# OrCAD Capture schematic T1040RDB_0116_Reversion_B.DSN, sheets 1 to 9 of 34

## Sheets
1 01 Page Listing: title: T1040RDB; rev: A
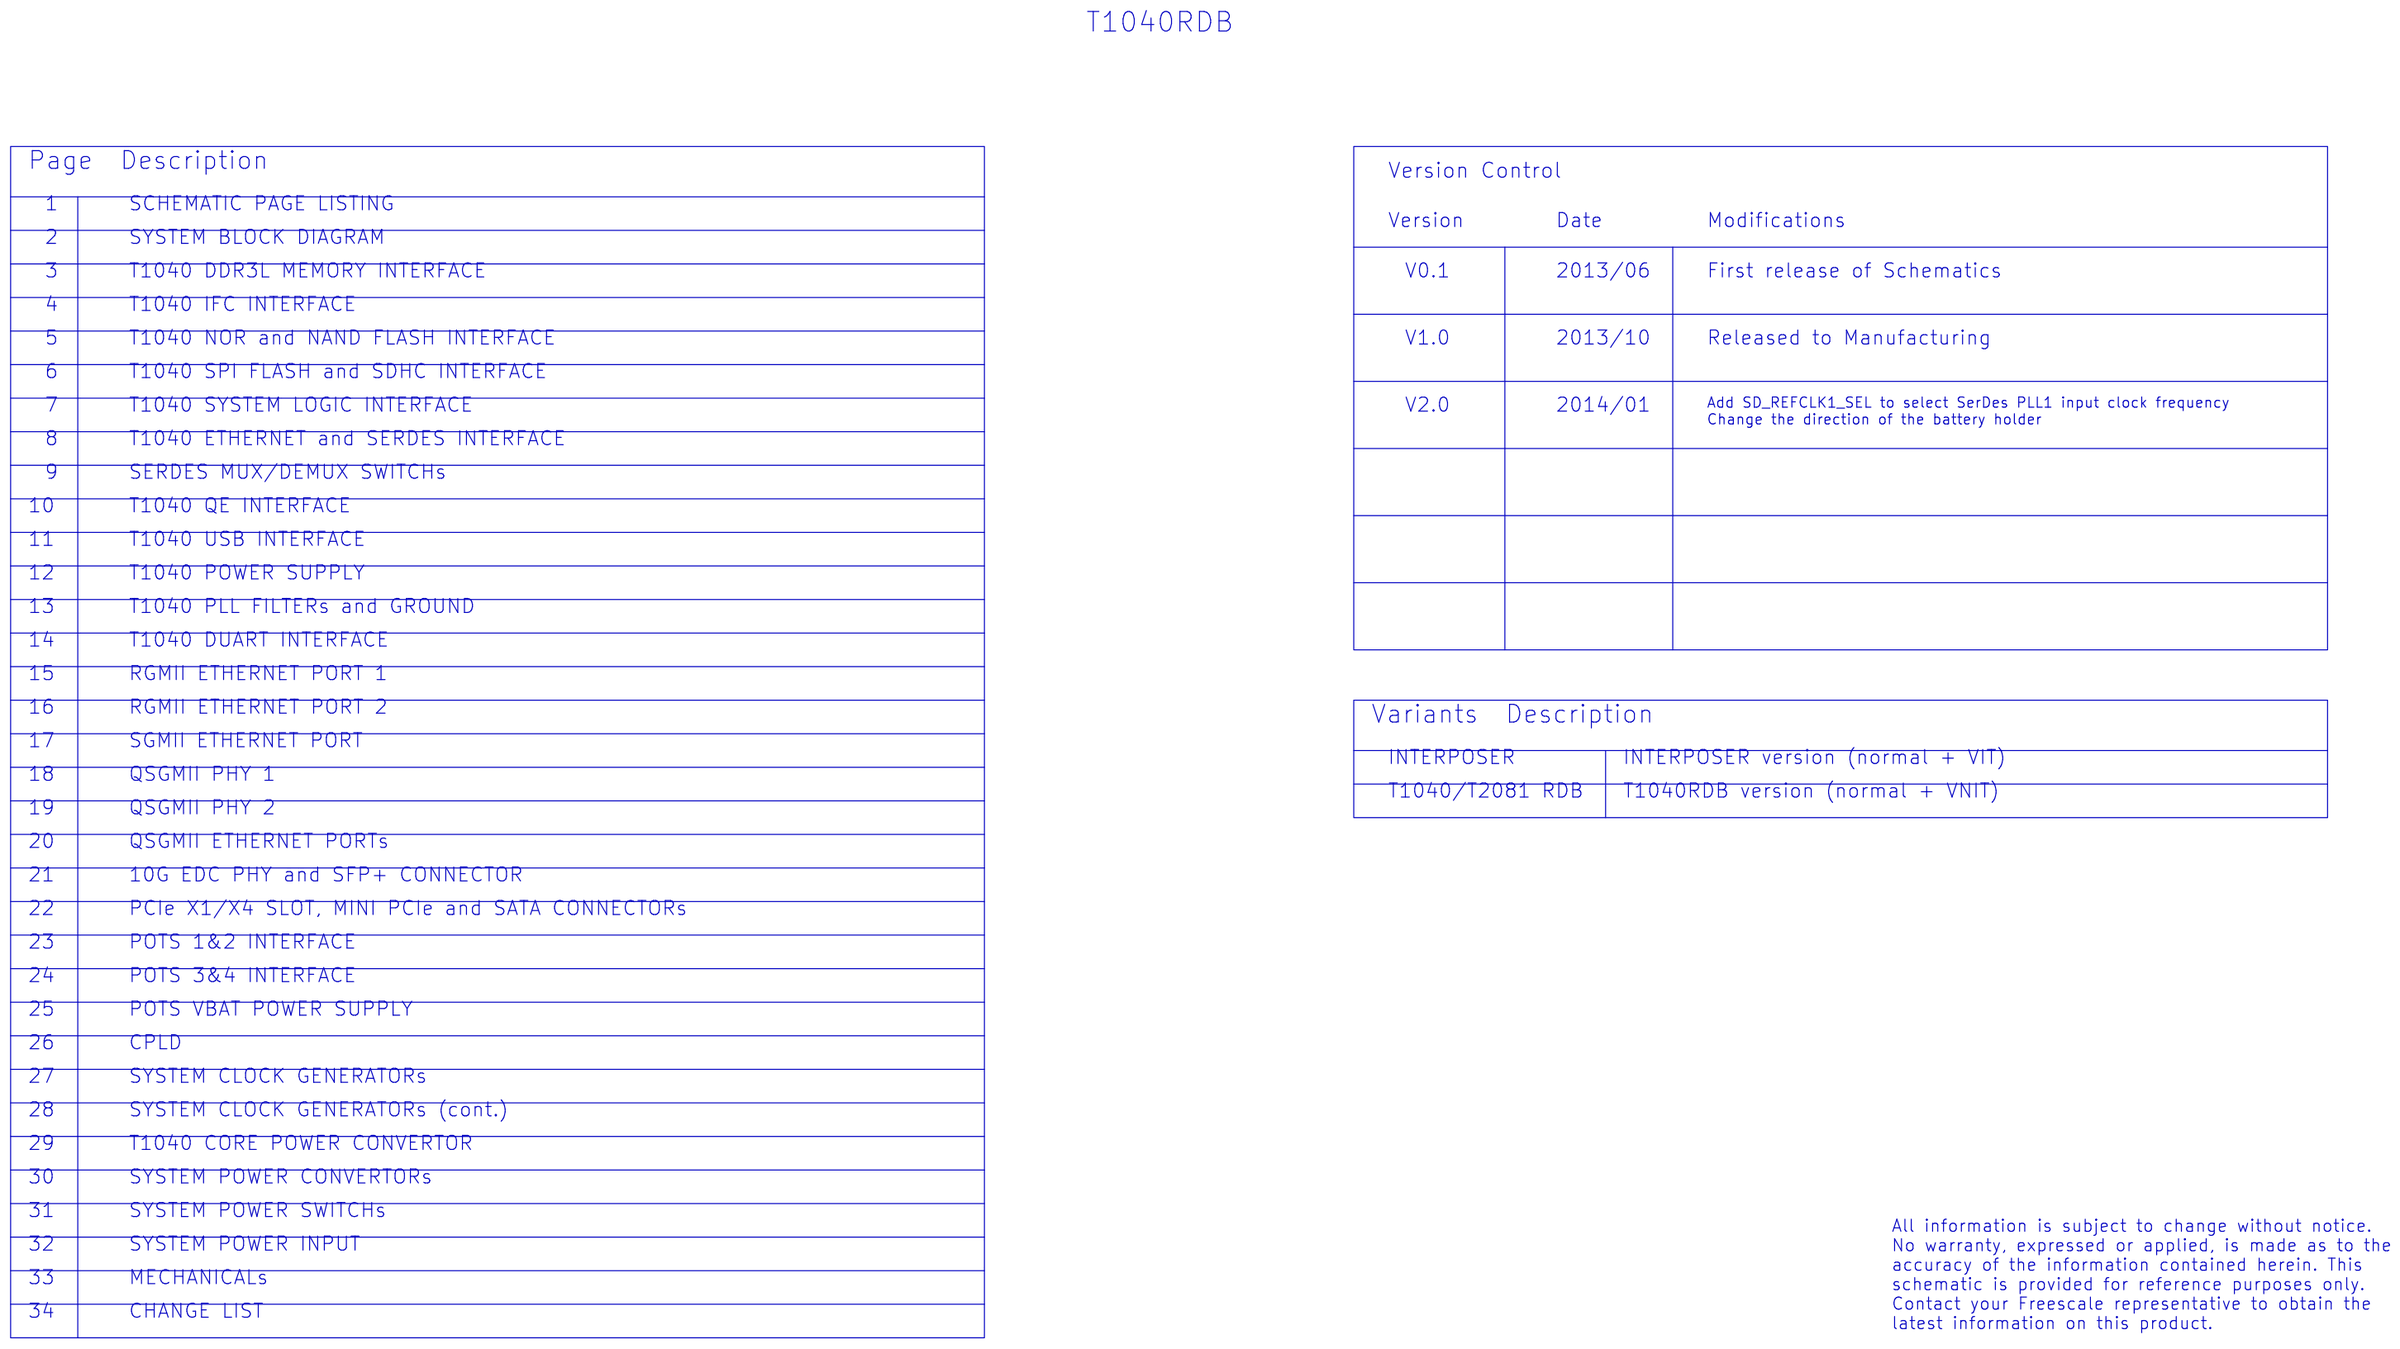
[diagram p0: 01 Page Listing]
2 02 Block Diagram
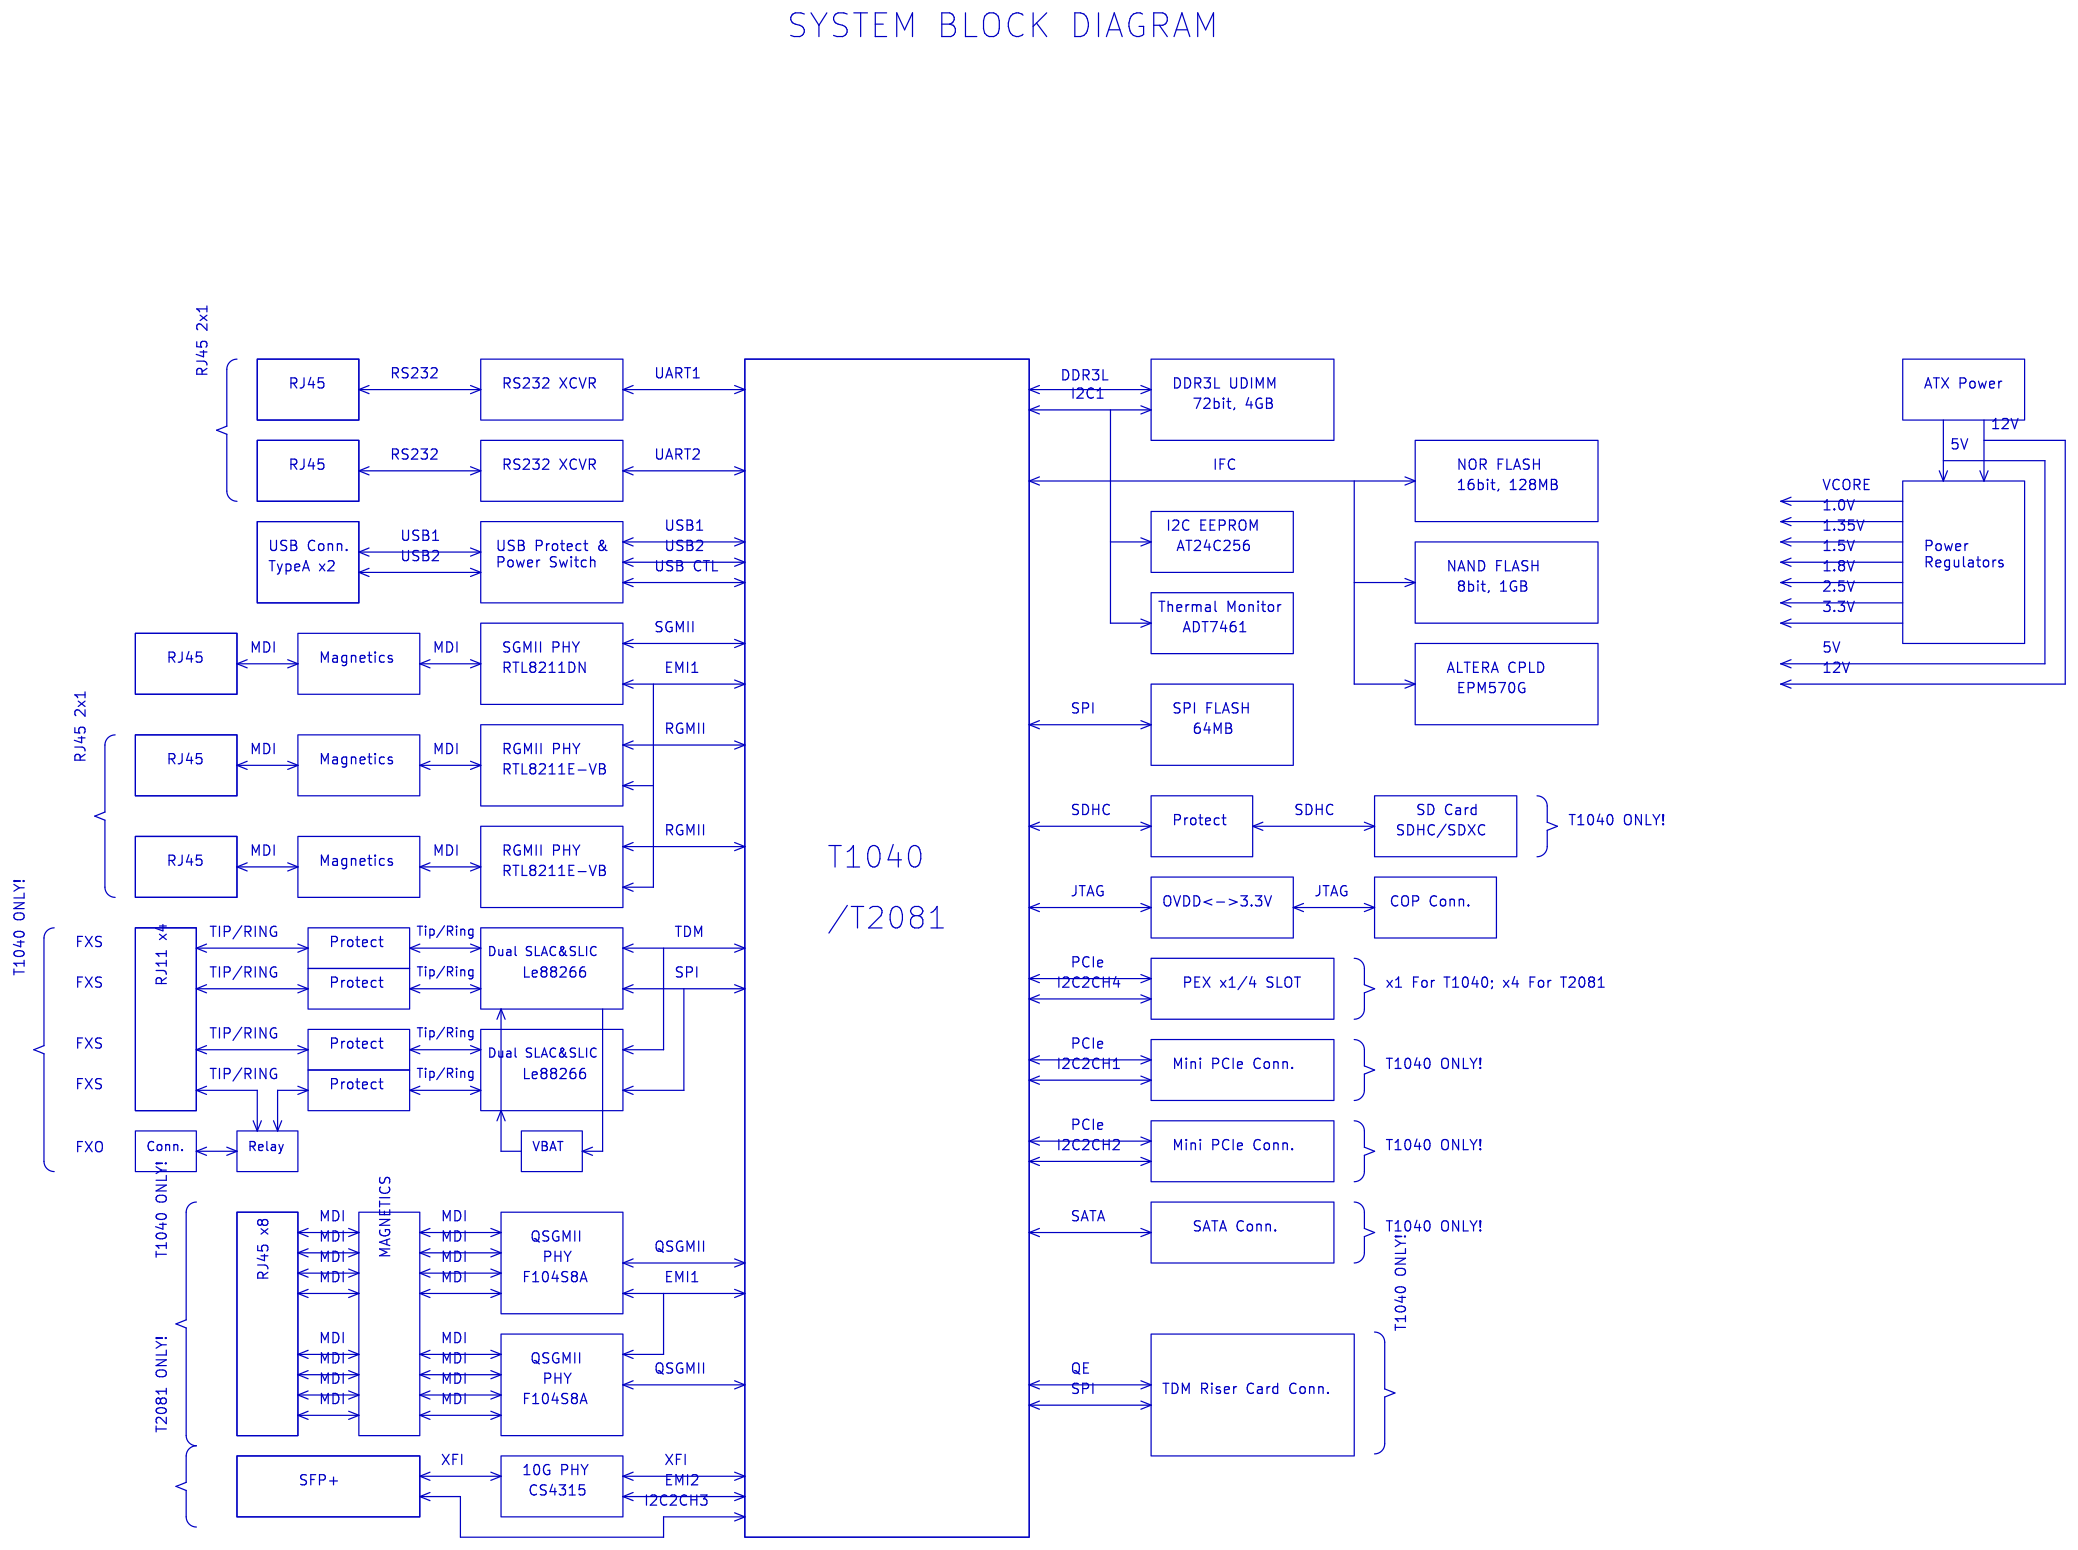
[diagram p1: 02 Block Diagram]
3 03 DDR3: size B
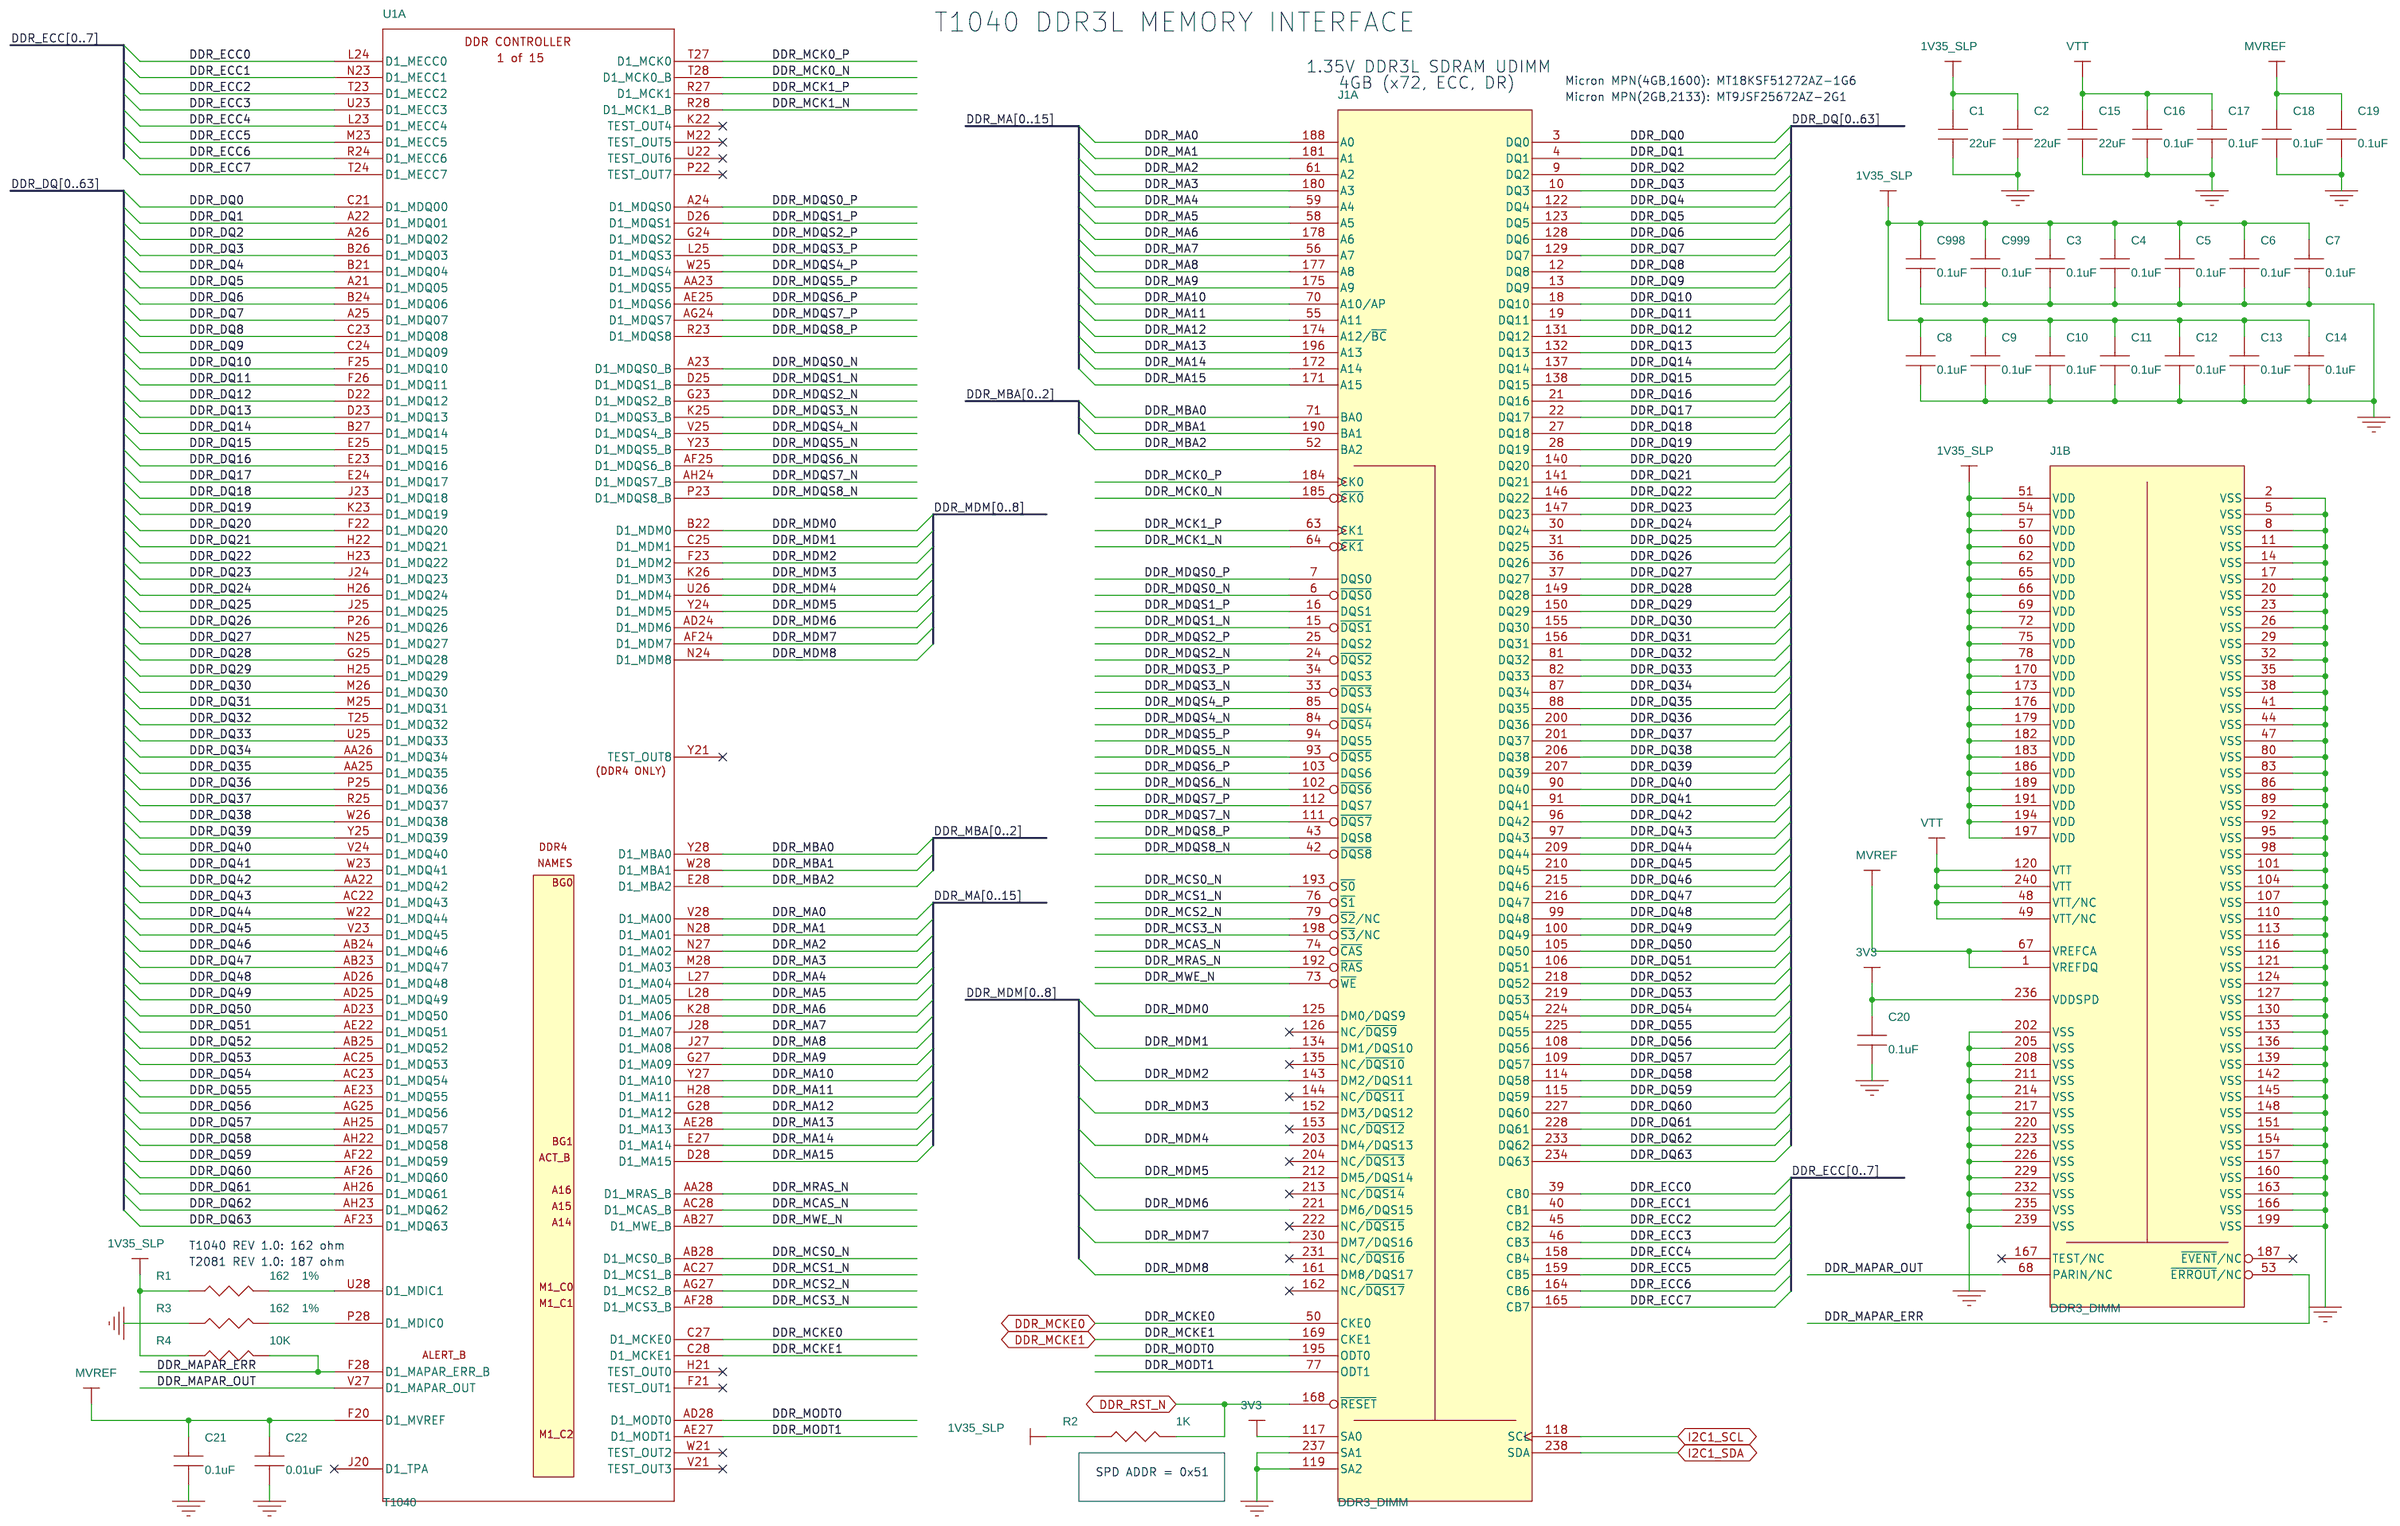
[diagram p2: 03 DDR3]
4 04 IFC: size B
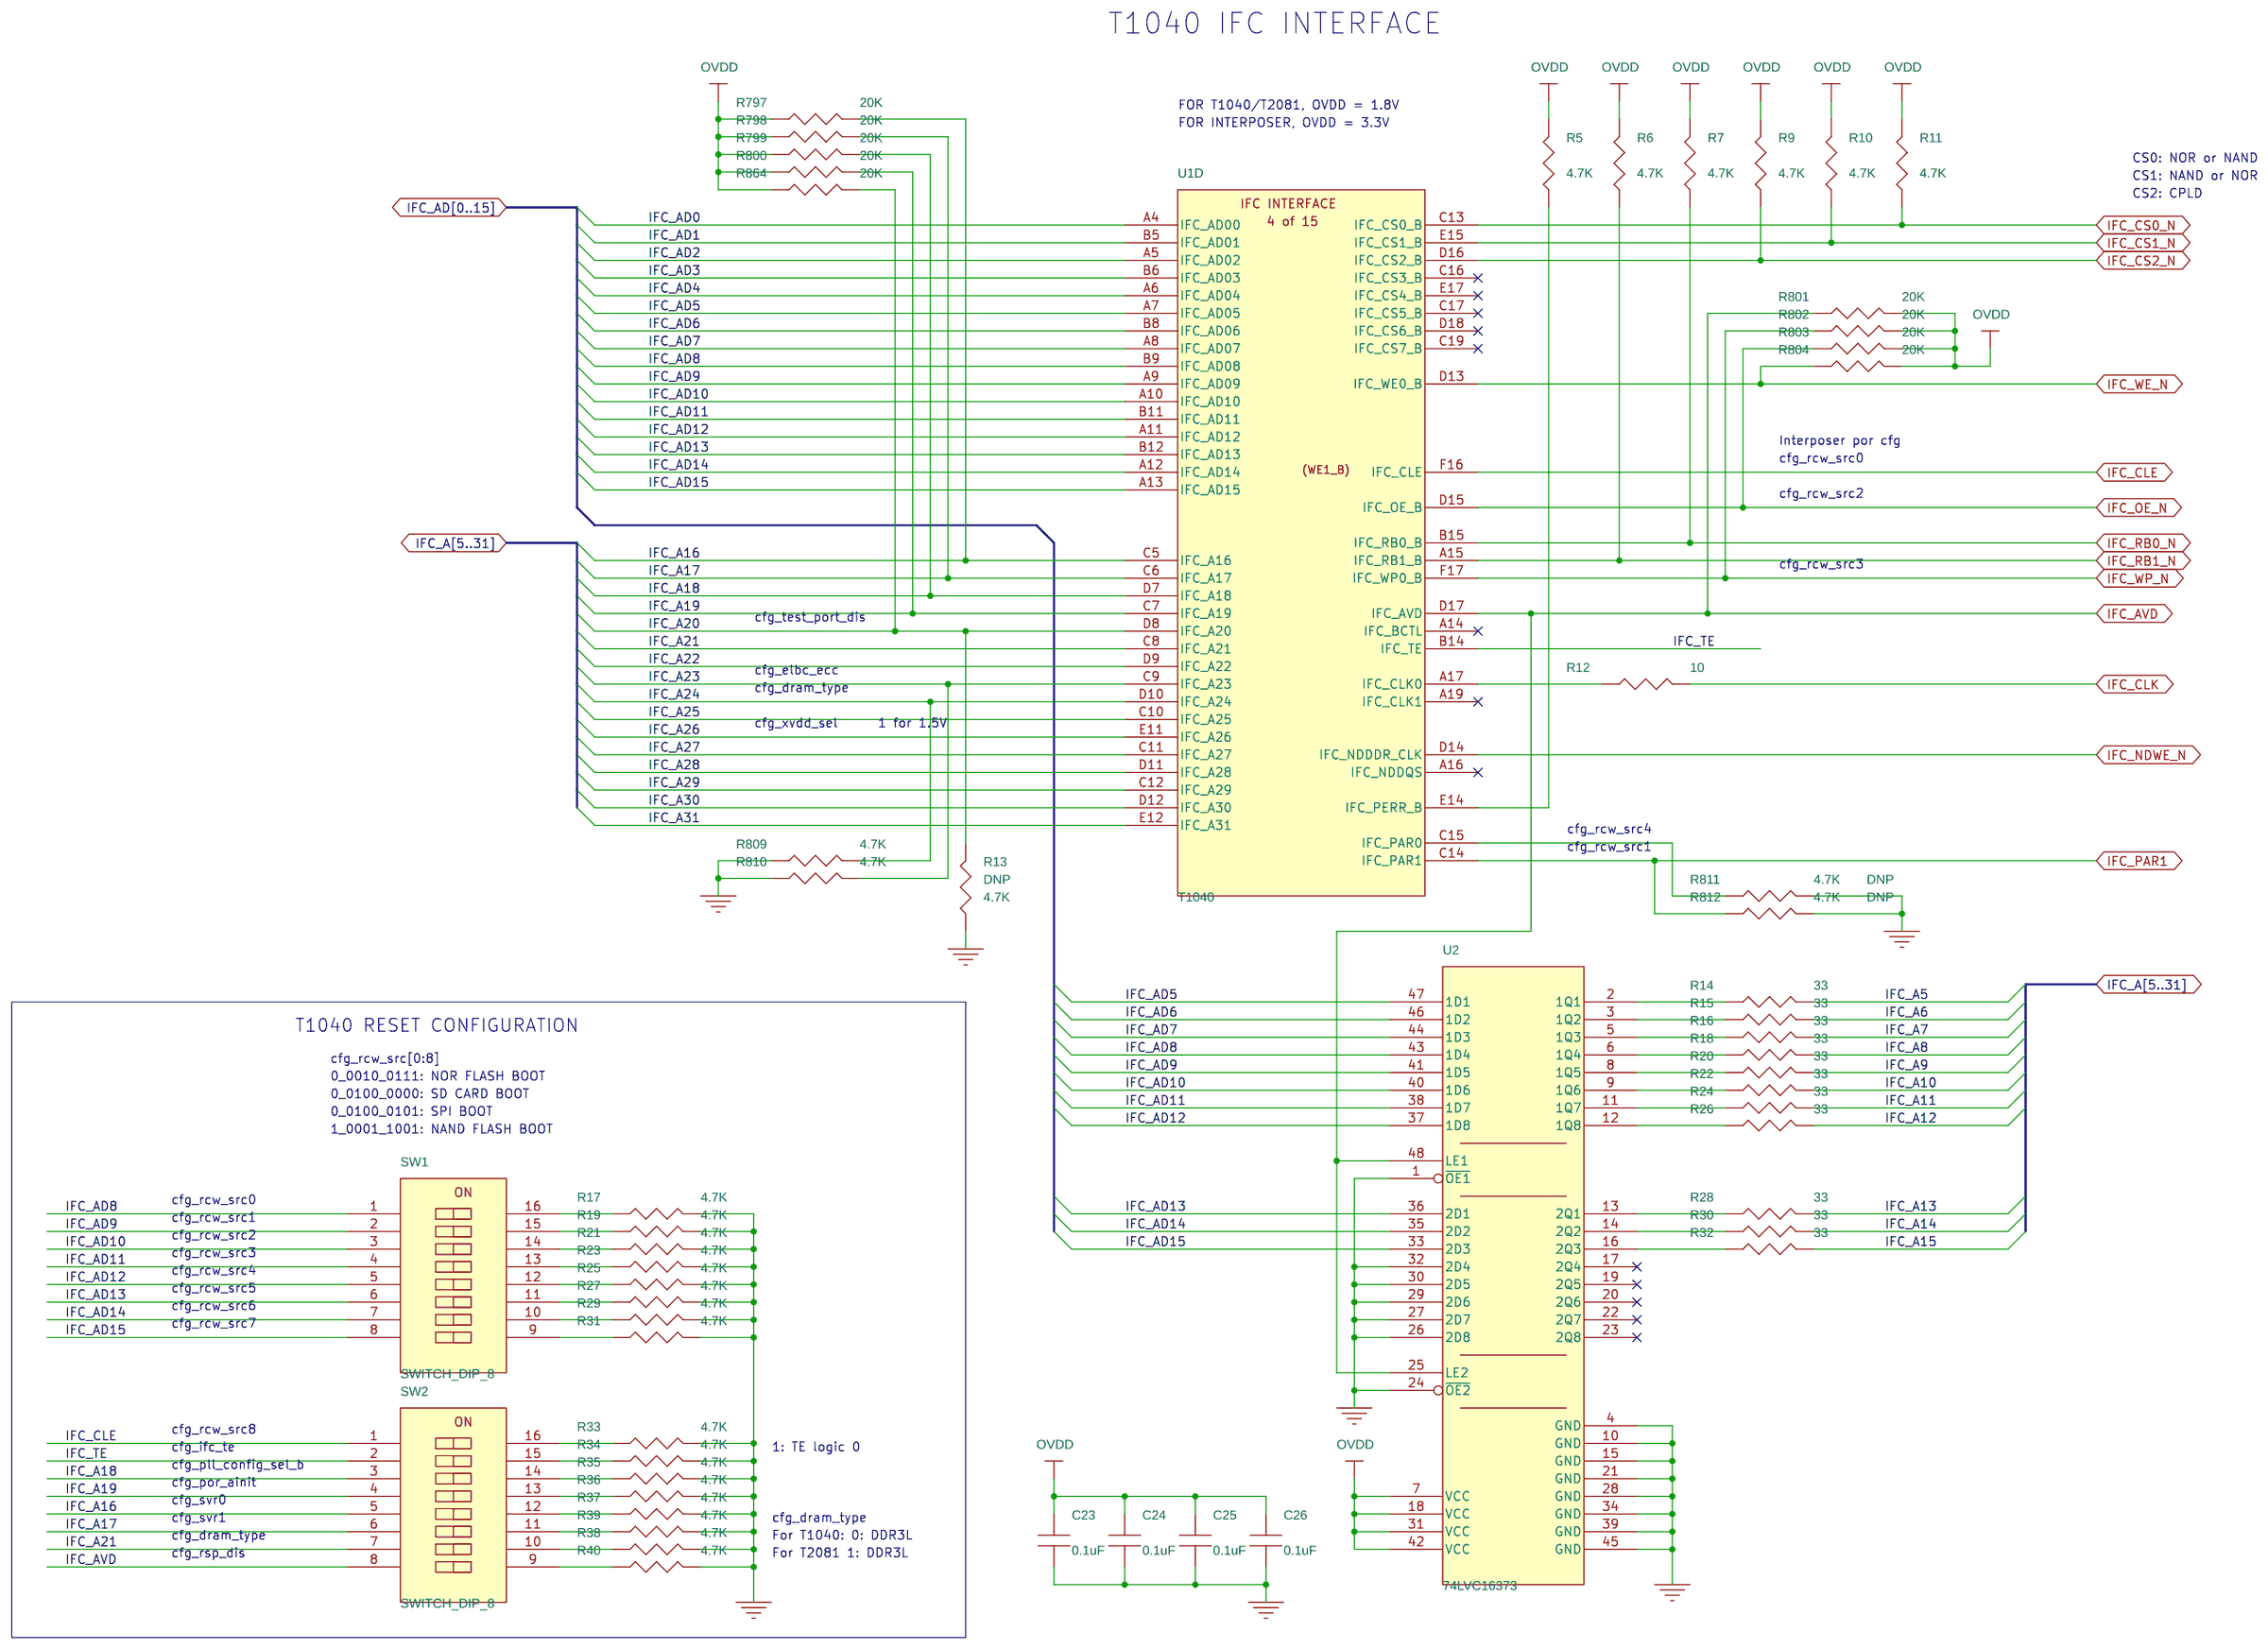
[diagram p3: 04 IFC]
5 05 Flash: size B
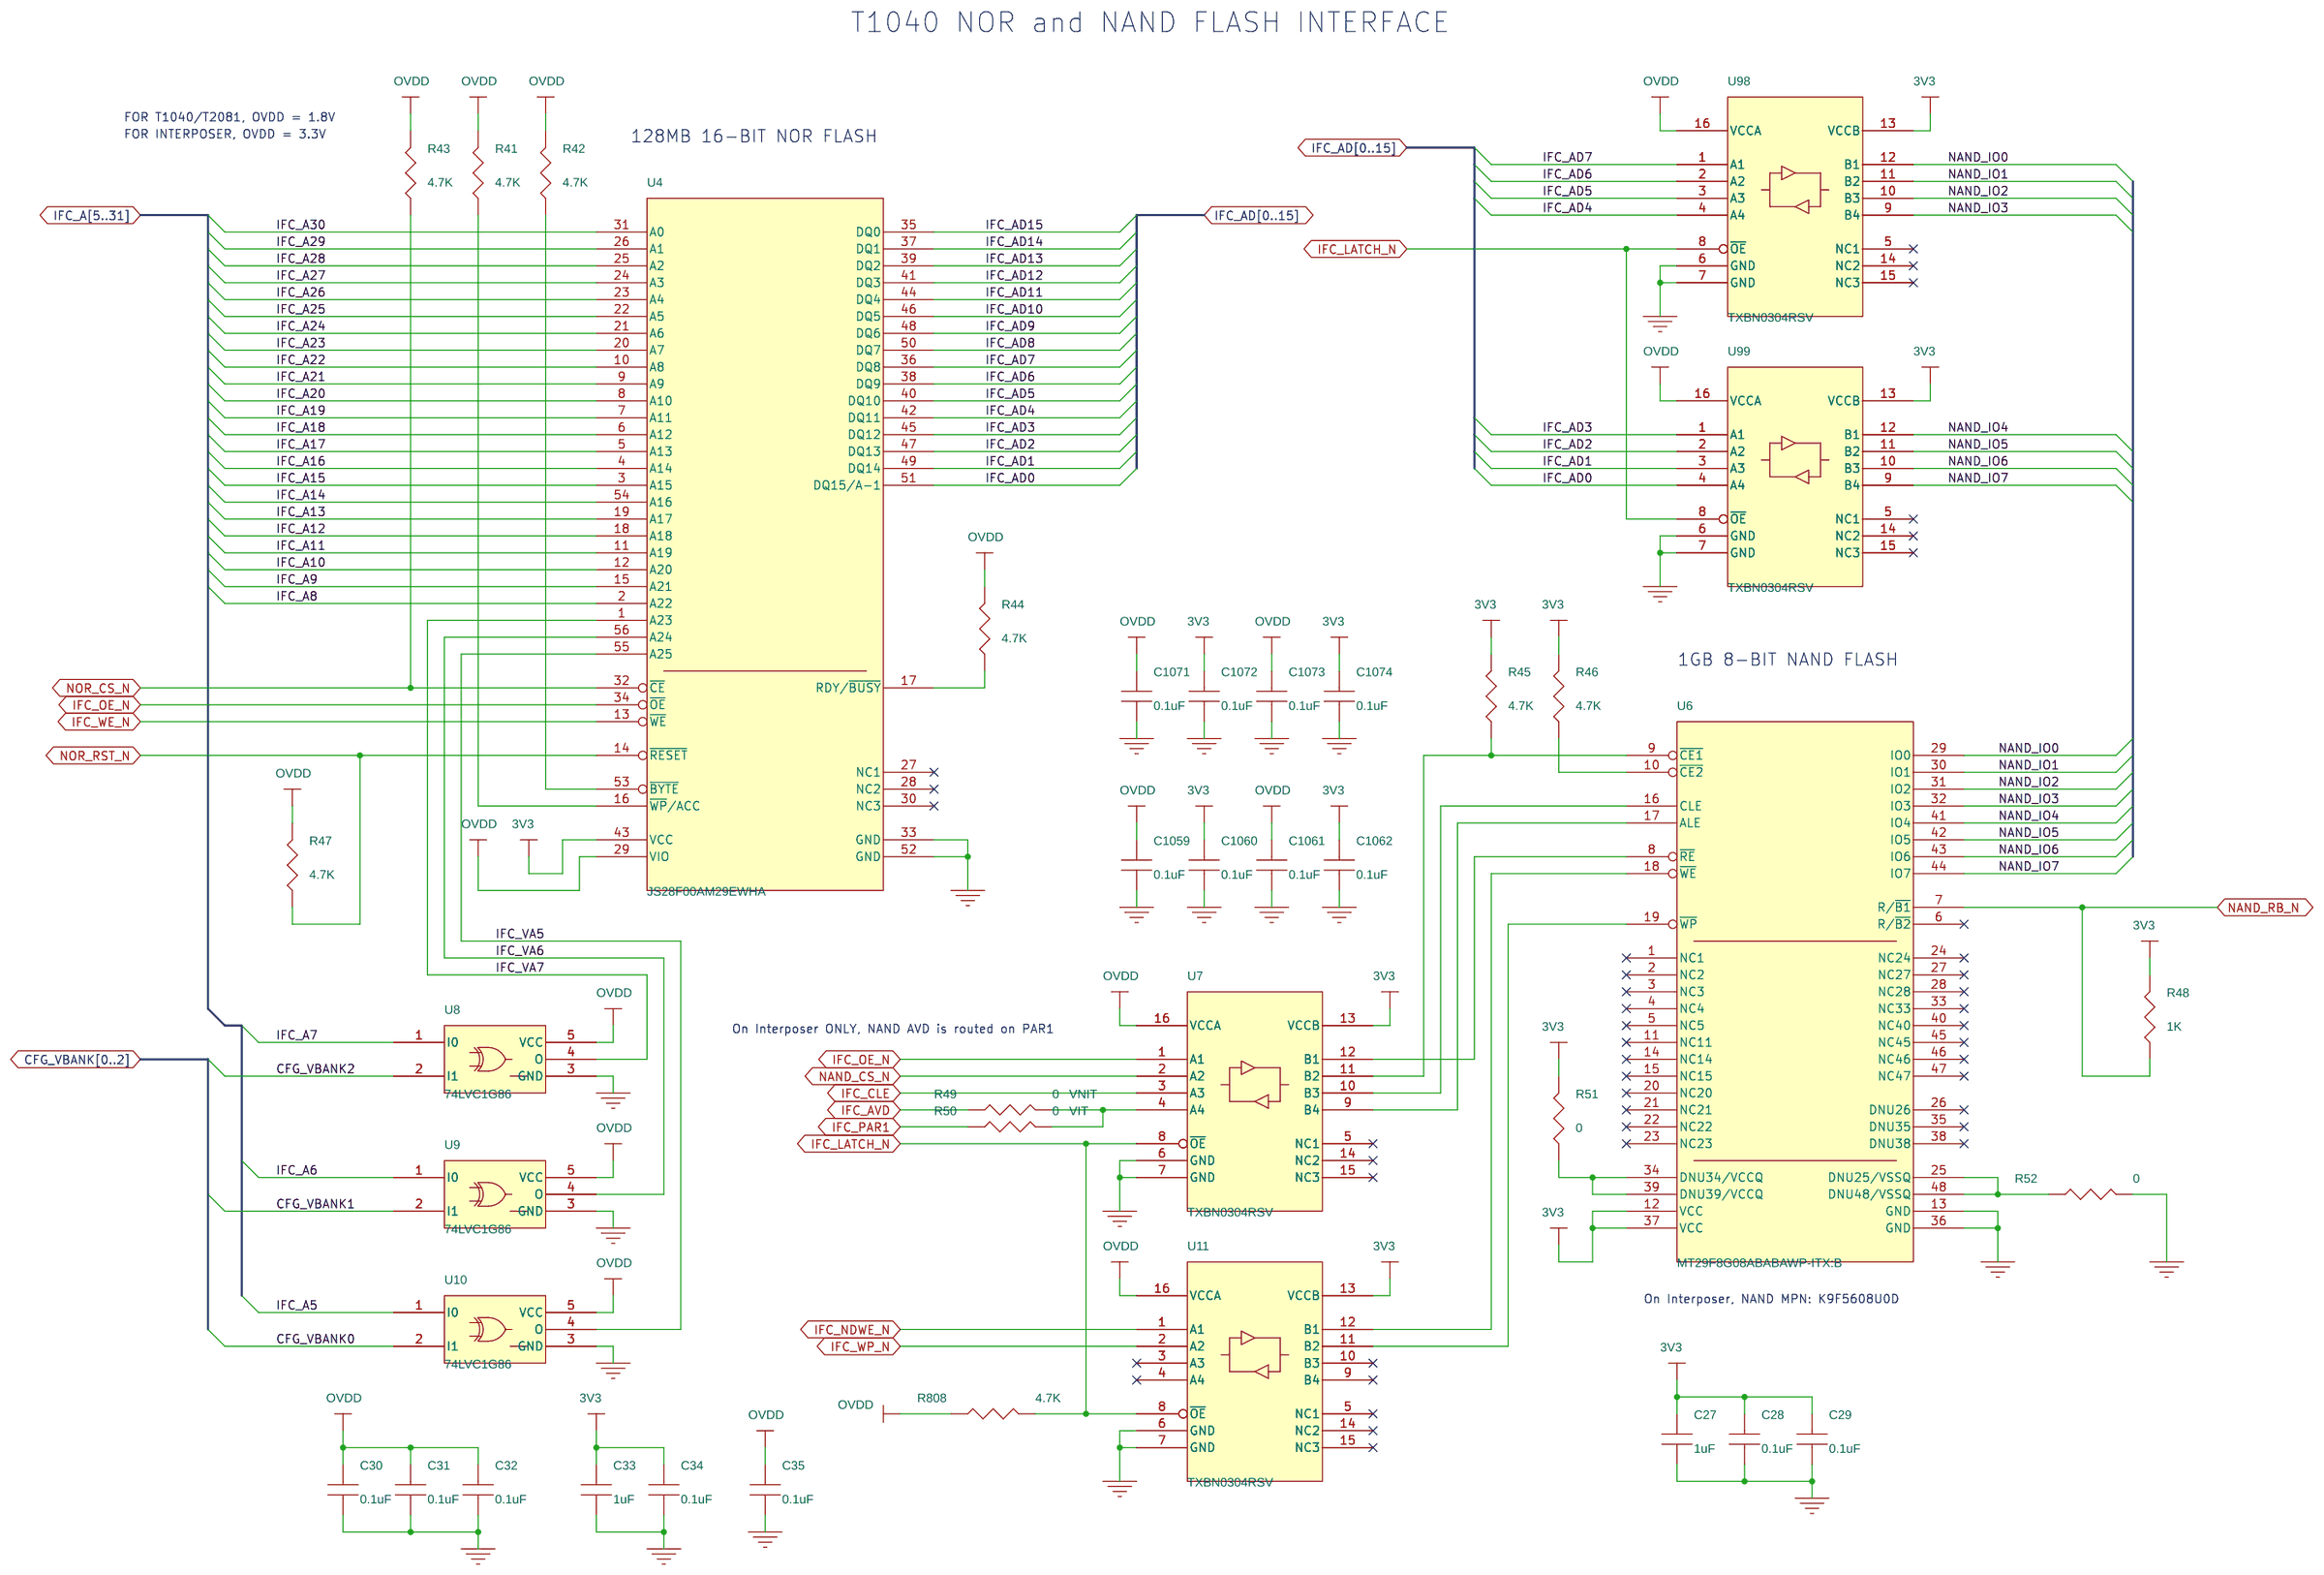
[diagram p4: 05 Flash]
6 06 SPI&SDHC: size B
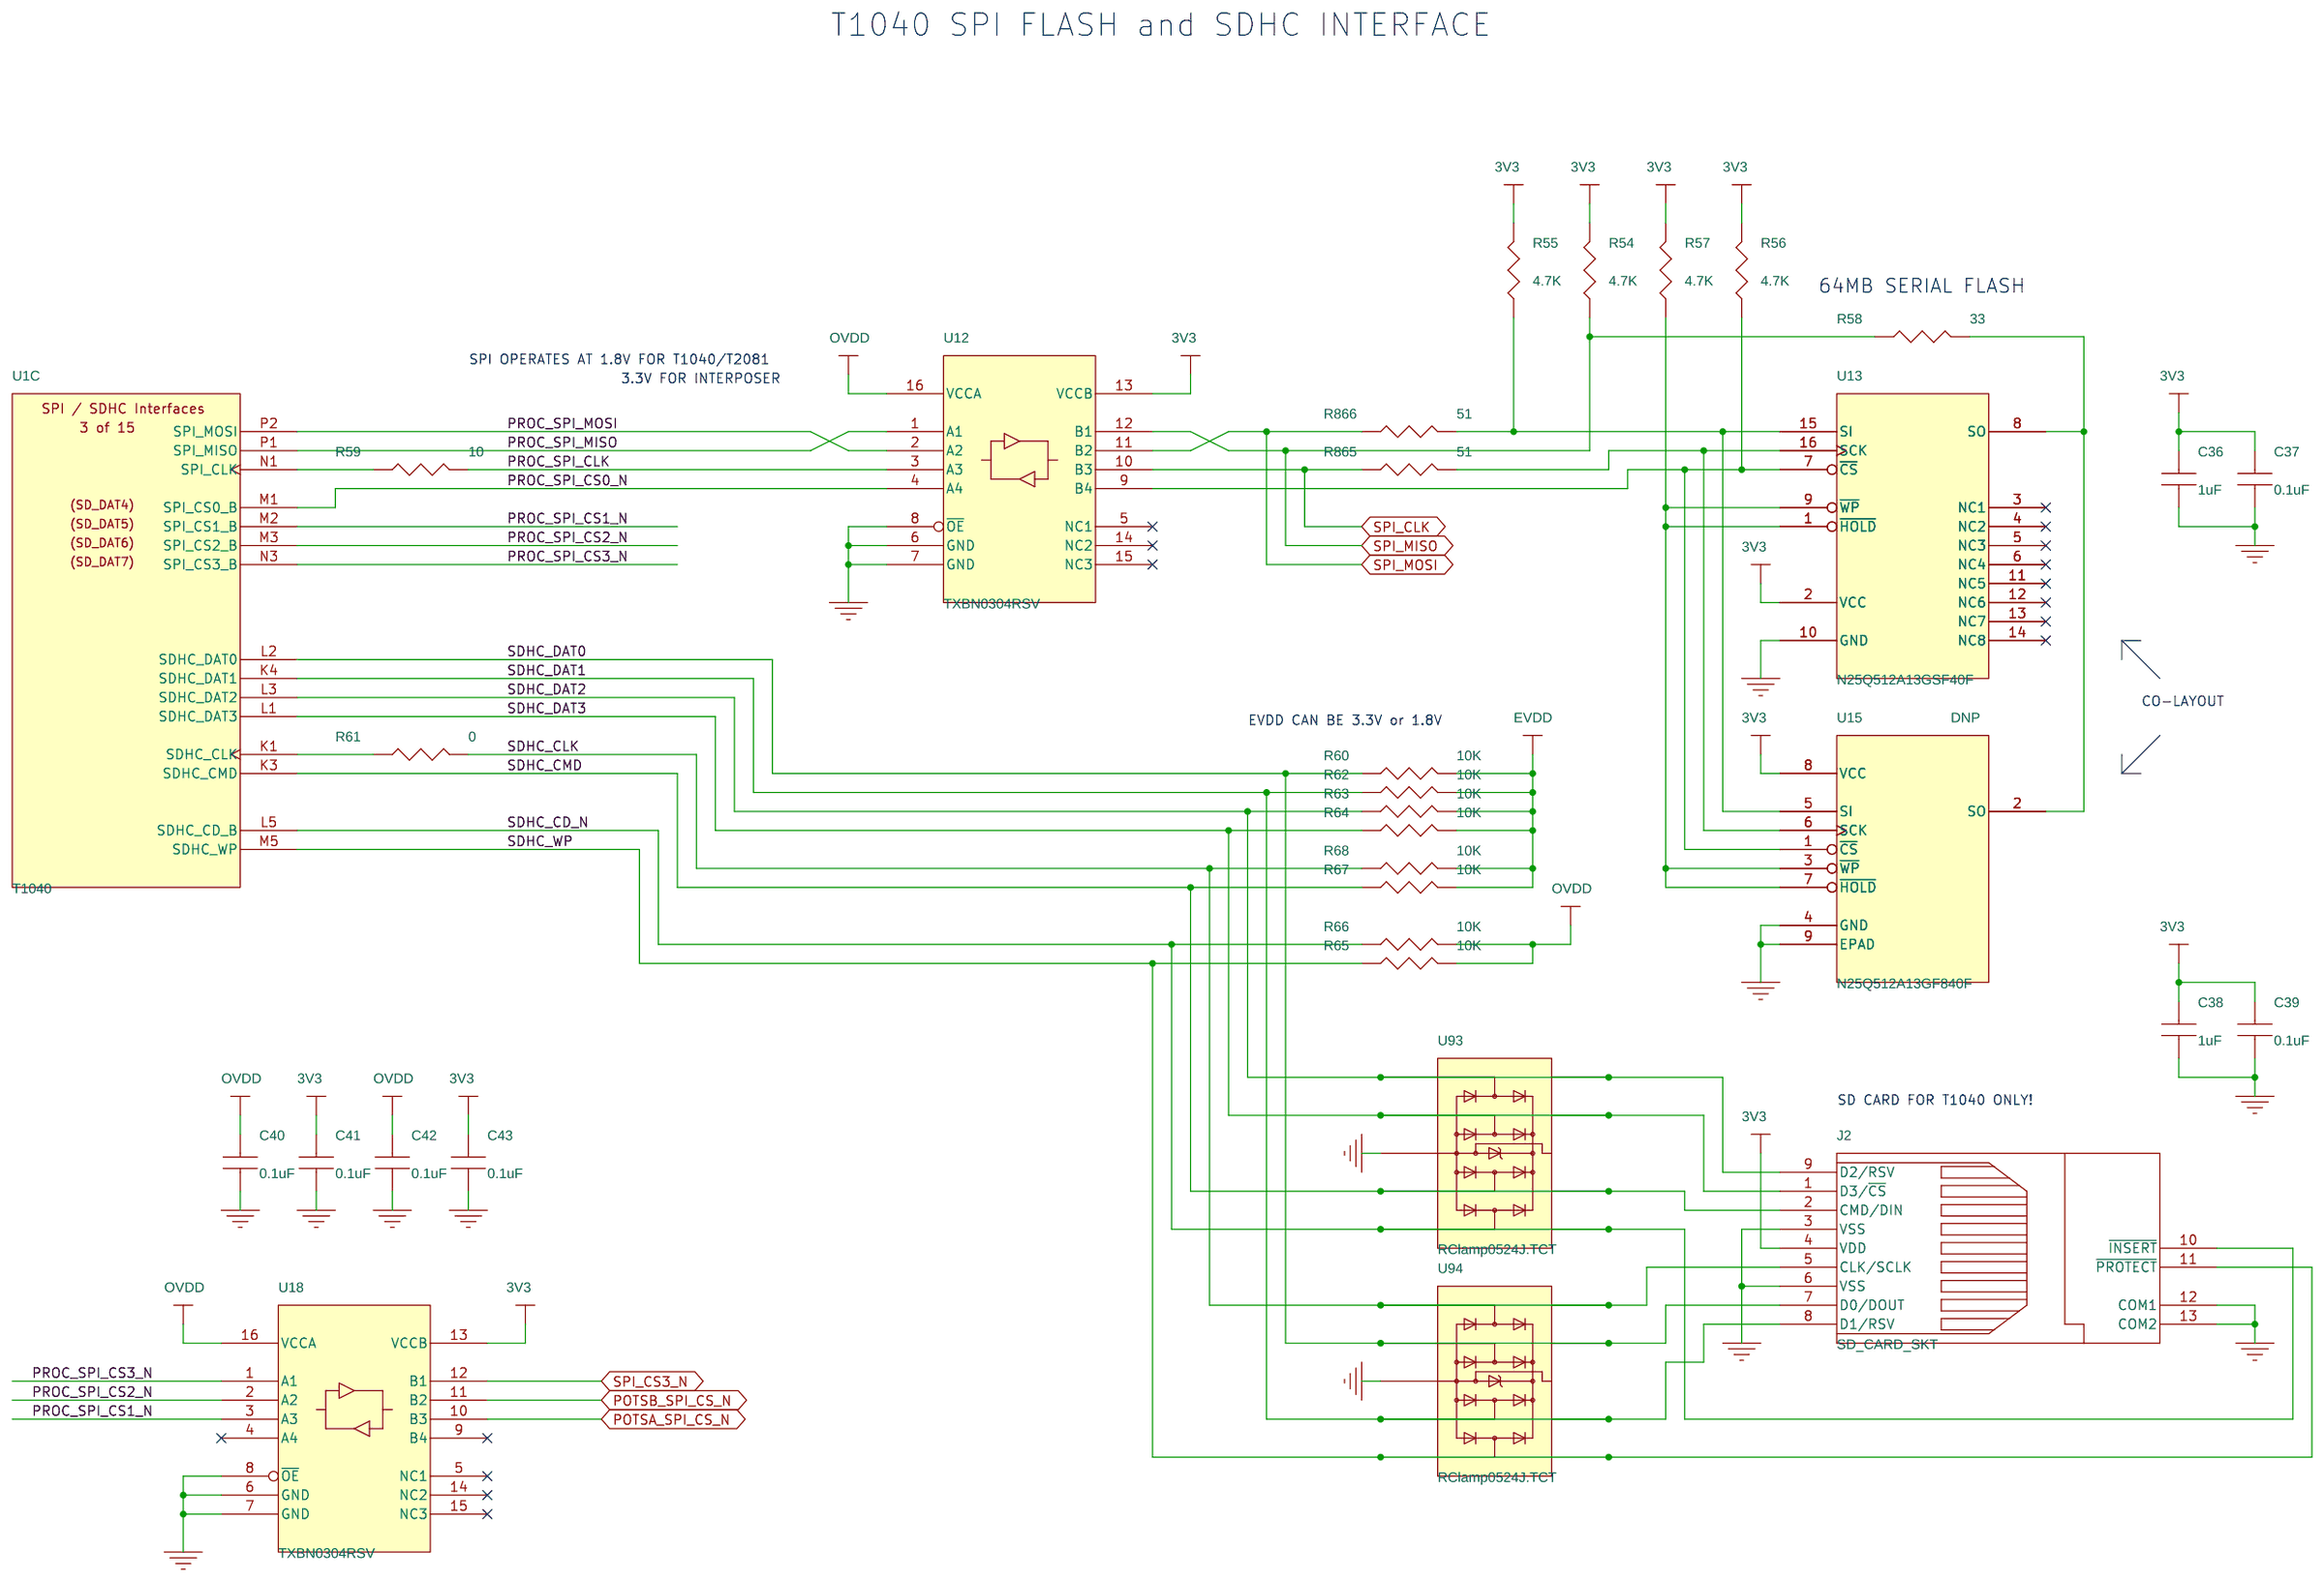
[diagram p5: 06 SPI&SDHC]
7 07 SYS: size B
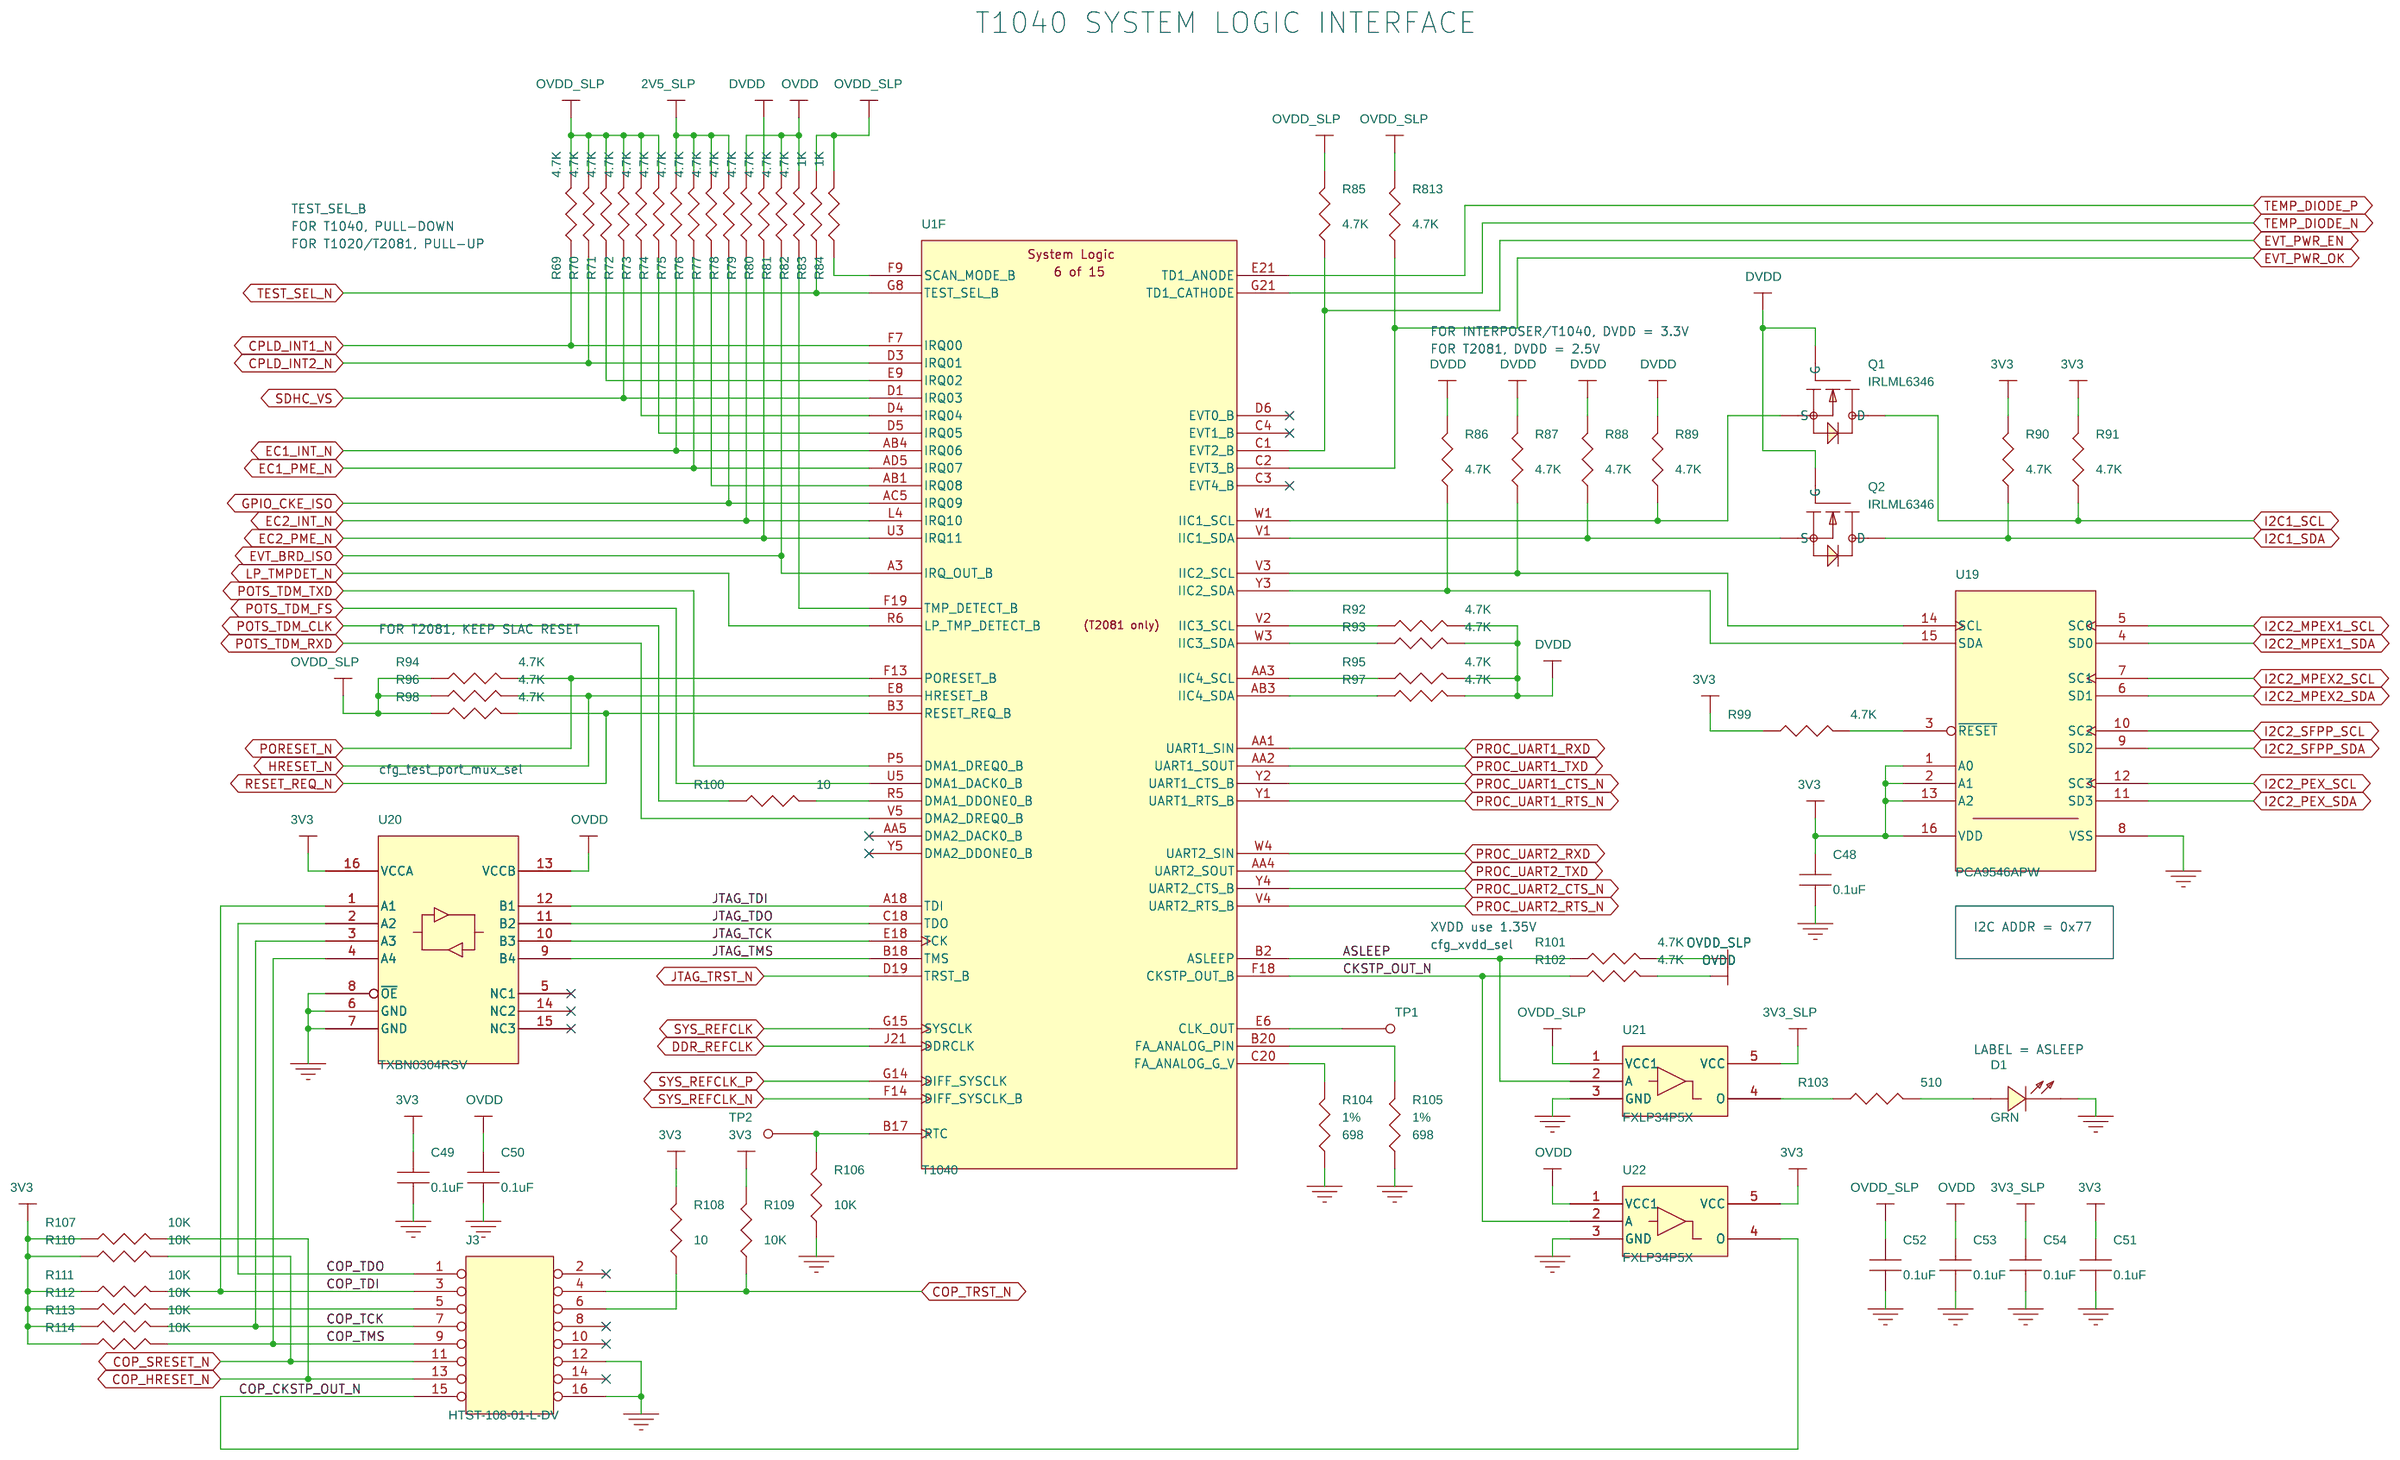
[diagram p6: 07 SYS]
8 08 EC&SD: size B
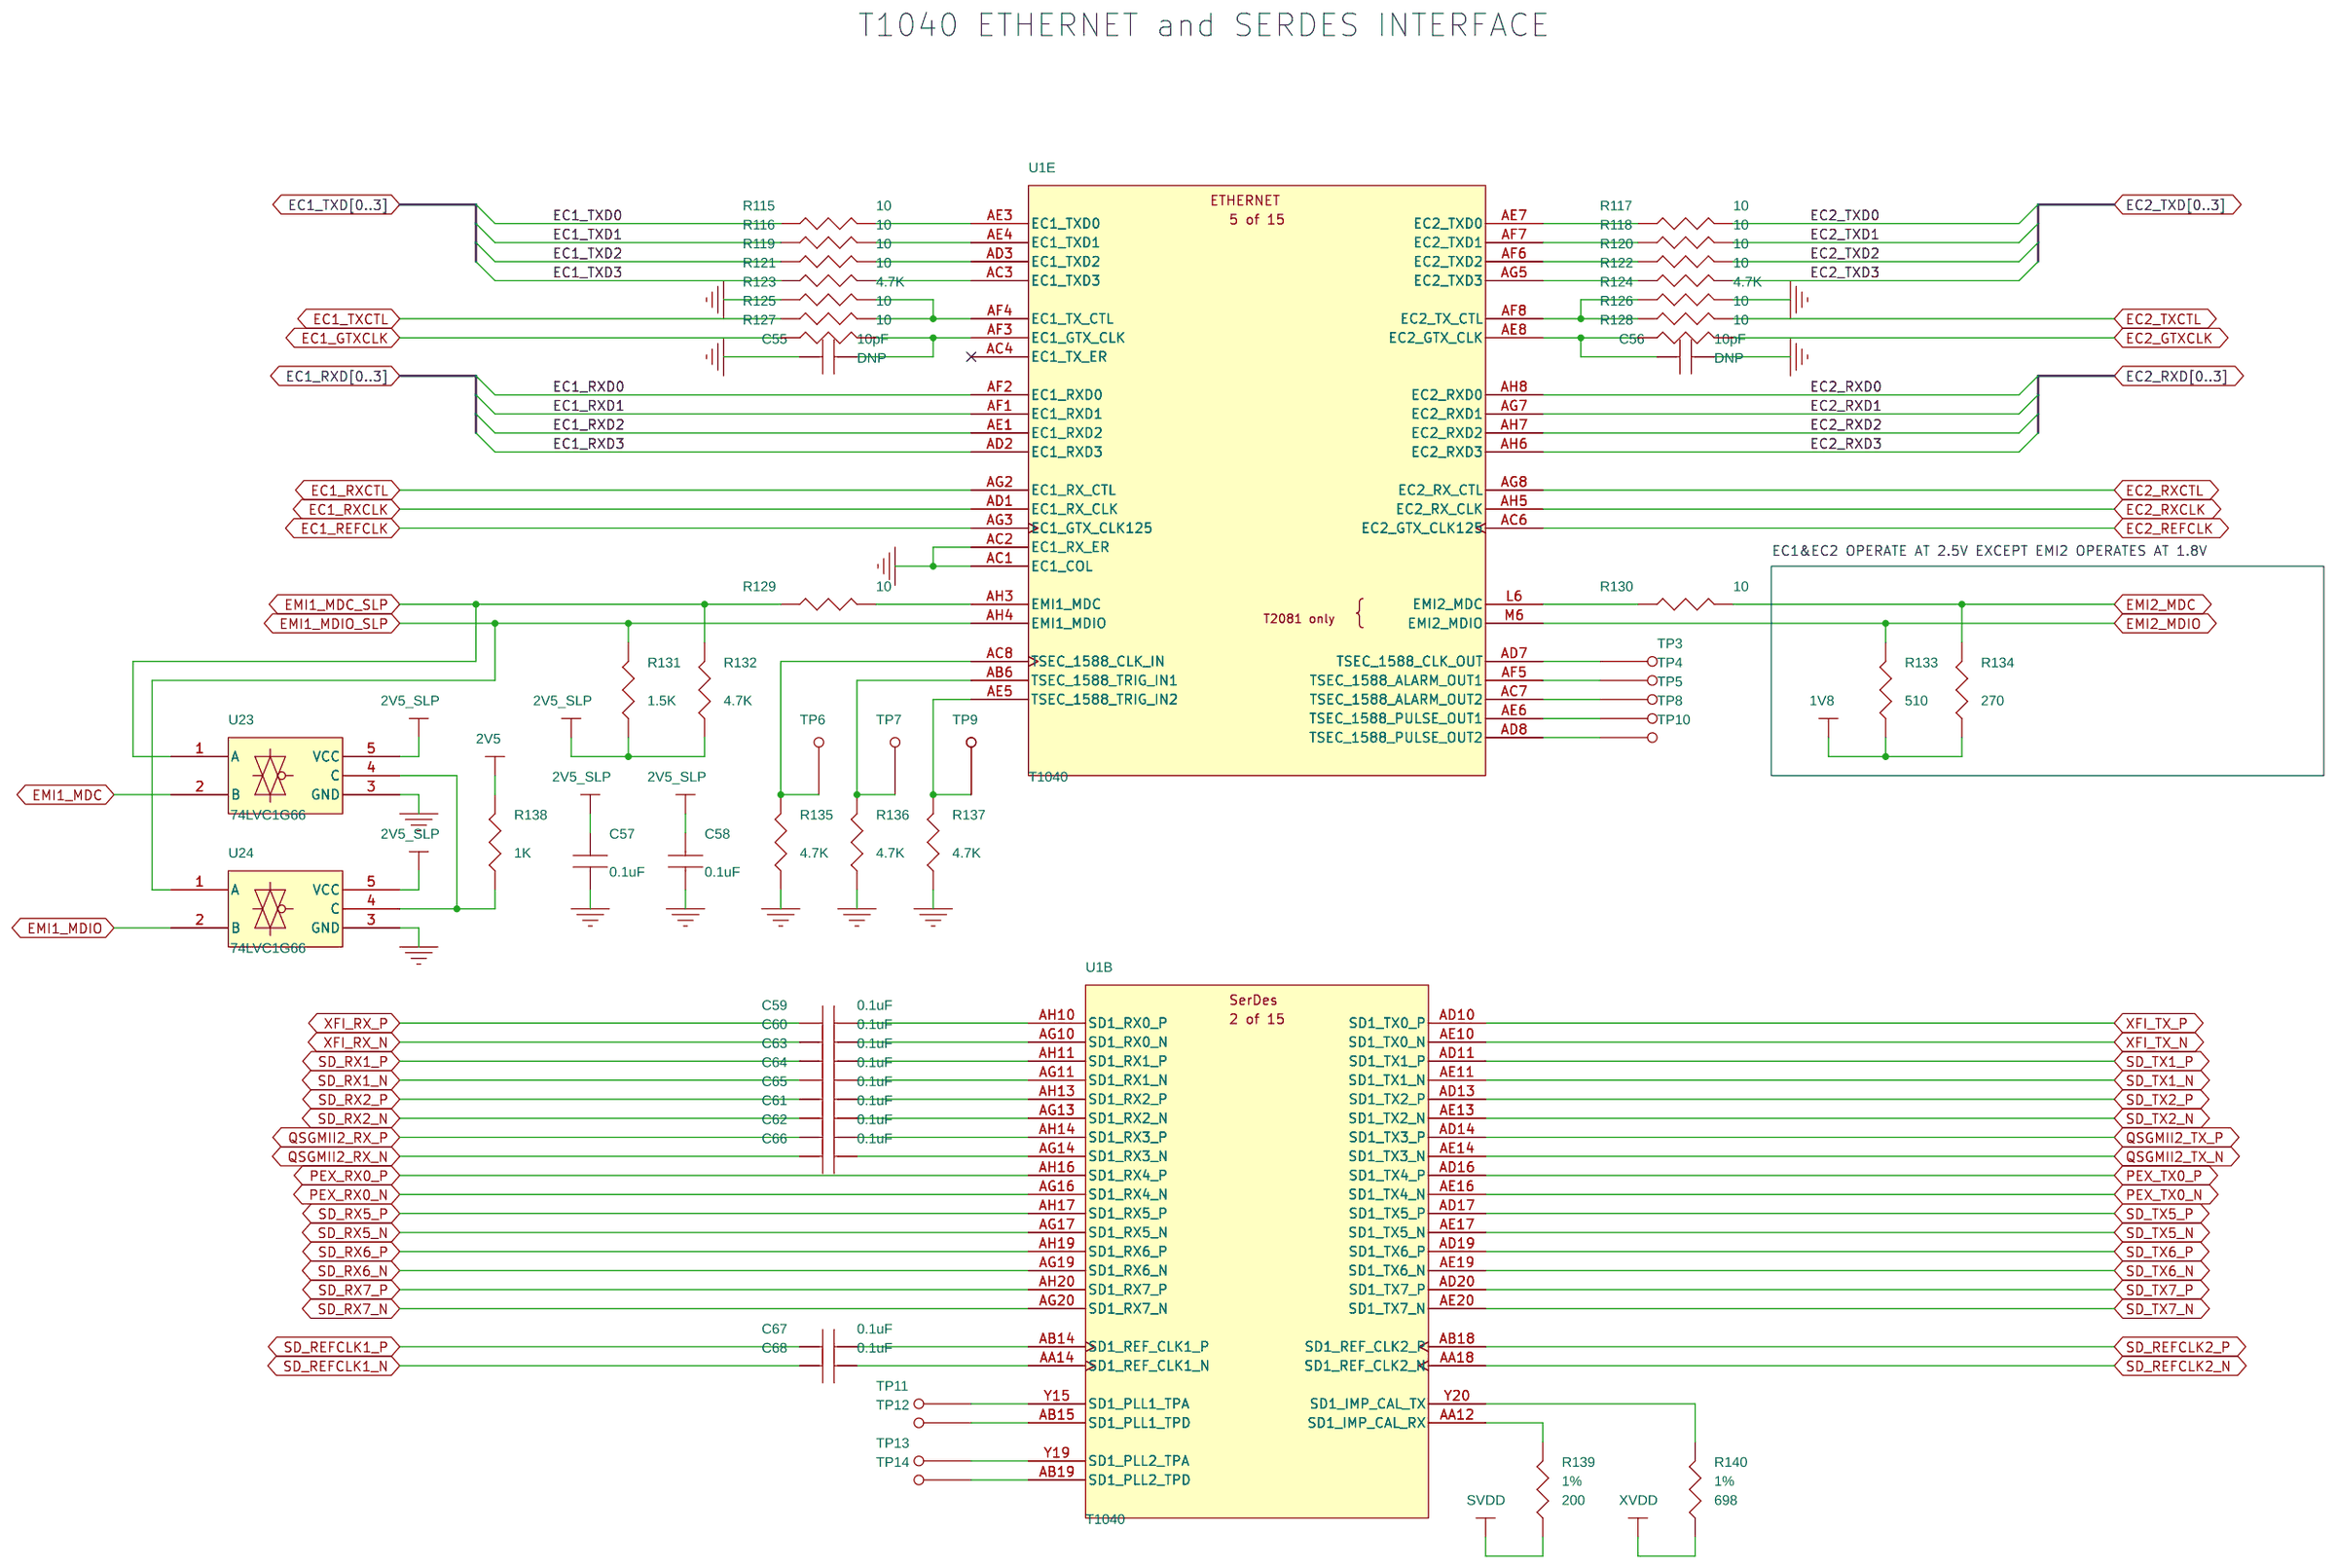
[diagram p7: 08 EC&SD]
9 09 SerDes Mux: size B
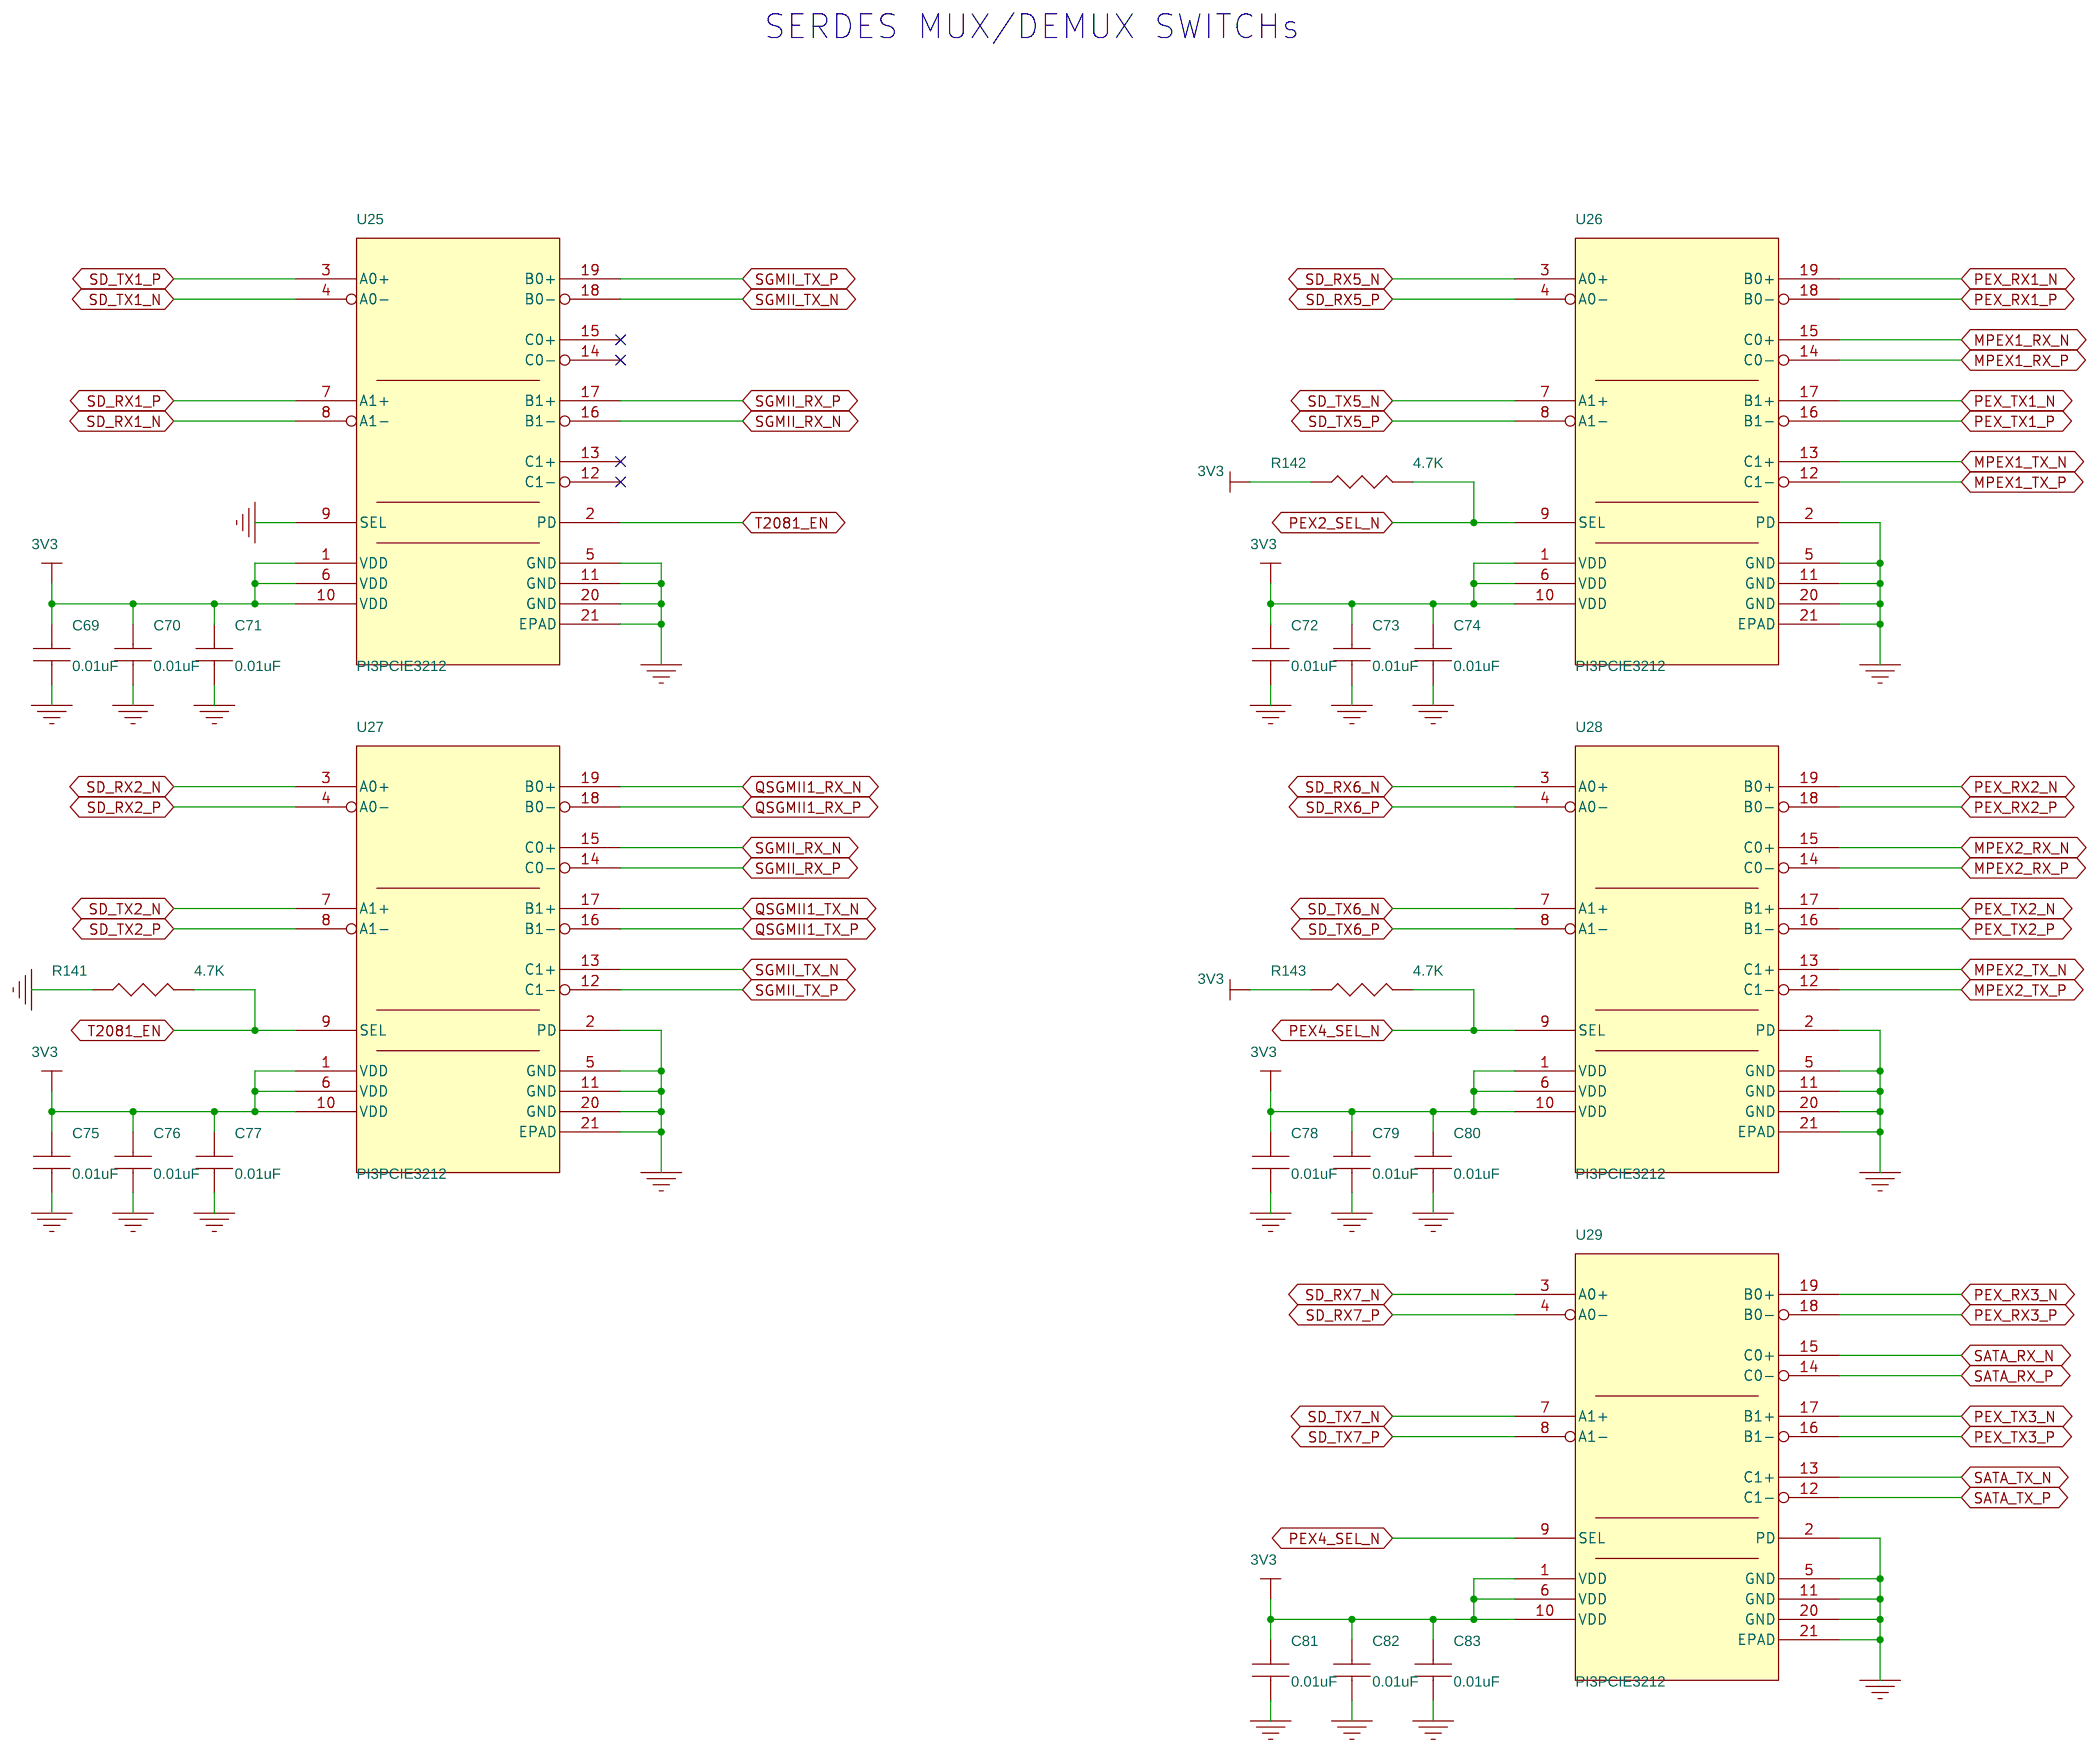
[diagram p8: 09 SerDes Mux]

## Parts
sheet 03 DDR3
C1  22uF  [0805]
C2  22uF  [0805]
C3  0.1uF  [0402]
C4  0.1uF  [0402]
C5  0.1uF  [0402]
C6  0.1uF  [0402]
C7  0.1uF  [0402]
C8  0.1uF  [0402]
C9  0.1uF  [0402]
C10  0.1uF  [0402]
C11  0.1uF  [0402]
C12  0.1uF  [0402]
C13  0.1uF  [0402]
C14  0.1uF  [0402]
C15  22uF  [0805]
C16  0.1uF  [0402]
C17  0.1uF  [0402]
C18  0.1uF  [0402]
C19  0.1uF  [0402]
C20  0.1uF  [0402]
C21  0.1uF  [0201]
C22  0.01uF  [0201]
C998  0.1uF  [0402]
C999  0.1uF  [0402]
J1  DDR3_DIMM  [con_ddr3_dimm]  (sections A,B)
R1  162  [0402]
R2  1K  [0402]
R3  162  [0402]
R4  10K  [0402]
sheet 04 IFC
C23  0.1uF  [0402]
C24  0.1uF  [0402]
C25  0.1uF  [0402]
C26  0.1uF  [0402]
R5  4.7K  [0402]
R6  4.7K  [0402]
R7  4.7K  [0402]
R9  4.7K  [0402]
R10  4.7K  [0402]
R11  4.7K  [0402]
R12  10  [0402]
R13  4.7K  [0402]
R14  33  [0402]
R15  33  [0402]
R16  33  [0402]
R17  4.7K  [0402]
R18  33  [0402]
R19  4.7K  [0402]
R20  33  [0402]
R21  4.7K  [0402]
R22  33  [0402]
R23  4.7K  [0402]
R24  33  [0402]
R25  4.7K  [0402]
R26  33  [0402]
R27  4.7K  [0402]
R28  33  [0402]
R29  4.7K  [0402]
R30  33  [0402]
R31  4.7K  [0402]
R32  33  [0402]
R33  4.7K  [0402]
R34  4.7K  [0402]
R35  4.7K  [0402]
R36  4.7K  [0402]
R37  4.7K  [0402]
R38  4.7K  [0402]
R39  4.7K  [0402]
R40  4.7K  [0402]
R797  20K  [0402]
R798  20K  [0402]
R799  20K  [0402]
R800  20K  [0402]
R801  20K  [0402]
R802  20K  [0402]
R803  20K  [0402]
R804  20K  [0402]
R809  4.7K  [0402]
R810  4.7K  [0402]
R811  4.7K  [0402]
R812  4.7K  [0402]
R864  20K  [0402]
SW1  SWITCH_DIP_8  [con_switch_x8]
SW2  SWITCH_DIP_8  [con_switch_x8]
U2  74LVC16373  [tssop_48w]
sheet 05 Flash
C27  1uF  [0402]
C28  0.1uF  [0402]
C29  0.1uF  [0402]
C30  0.1uF  [0402]
C31  0.1uF  [0402]
C32  0.1uF  [0402]
C33  1uF  [0402]
C34  0.1uF  [0402]
C35  0.1uF  [0402]
C1059  0.1uF  [0402]
C1060  0.1uF  [0402]
C1061  0.1uF  [0402]
C1062  0.1uF  [0402]
C1071  0.1uF  [0402]
C1072  0.1uF  [0402]
C1073  0.1uF  [0402]
C1074  0.1uF  [0402]
R41  4.7K  [0402]
R42  4.7K  [0402]
R43  4.7K  [0402]
R44  4.7K  [0402]
R45  4.7K  [0402]
R46  4.7K  [0402]
R47  4.7K  [0402]
R48  1K  [0402]
R49  0  [0402]
R50  0  [0402]
R51  0  [0402]
R52  0  [0402]
R808  4.7K  [0402]
U4  JS28F00AM29EWHA  [tsop1_56]
U6  MT29F8G08ABABAWP-ITX:B  [tsop1_48]
U7  TXBN0304RSV  [qfn_p040_d040_b260x180_16]
U8  74LVC1G86  [sc70_5]
U9  74LVC1G86  [sc70_5]
U10  74LVC1G86  [sc70_5]
U11  TXBN0304RSV  [qfn_p040_d040_b260x180_16]
U98  TXBN0304RSV  [qfn_p040_d040_b260x180_16]
U99  TXBN0304RSV  [qfn_p040_d040_b260x180_16]
sheet 06 SPI&SDHC
C36  1uF  [0402]
C37  0.1uF  [0402]
C38  1uF  [0402]
C39  0.1uF  [0402]
C40  0.1uF  [0402]
C41  0.1uF  [0402]
C42  0.1uF  [0402]
C43  0.1uF  [0402]
J2  SD_CARD_SKT  [con_sd]
R54  4.7K  [0402]
R55  4.7K  [0402]
R56  4.7K  [0402]
R57  4.7K  [0402]
R58  33  [0402]
R59  10  [0402]
R60  10K  [0402]
R61  0  [0402]
R62  10K  [0402]
R63  10K  [0402]
R64  10K  [0402]
R65  10K  [0402]
R66  10K  [0402]
R67  10K  [0402]
R68  10K  [0402]
R865  51  [0402]
R866  51  [0402]
U12  TXBN0304RSV  [qfn_p040_d040_b260x180_16]
U13  N25Q512A13GSF40F  [so_16l]
U15  N25Q512A13GF840F  [wson_8]
U18  TXBN0304RSV  [qfn_p040_d040_b260x180_16]
U93  RClamp0524J.TCT  [tvs_slp2710p8]
U94  RClamp0524J.TCT  [tvs_slp2710p8]
sheet 07 SYS
C48  0.1uF  [0402]
C49  0.1uF  [0402]
C50  0.1uF  [0402]
C51  0.1uF  [0402]
C52  0.1uF  [0402]
C53  0.1uF  [0402]
C54  0.1uF  [0402]
D1  GRN  [led_0603]
J3  HTST-108-01-L-DV  [hdr_p254_htst_2x8]
Q1  IRLML6346  [sot23]
Q2  IRLML6346  [sot23]
R69  4.7K  [0402]
R70  4.7K  [0402]
R71  4.7K  [0402]
R72  4.7K  [0402]
R73  4.7K  [0402]
R74  4.7K  [0402]
R75  4.7K  [0402]
R76  4.7K  [0402]
R77  4.7K  [0402]
R78  4.7K  [0402]
R79  4.7K  [0402]
R80  4.7K  [0402]
R81  4.7K  [0402]
R82  4.7K  [0402]
R83  1K  [0402]
R84  1K  [0402]
R85  4.7K  [0402]
R86  4.7K  [0402]
R87  4.7K  [0402]
R88  4.7K  [0402]
R89  4.7K  [0402]
R90  4.7K  [0402]
R91  4.7K  [0402]
R92  4.7K  [0402]
R93  4.7K  [0402]
R94  4.7K  [0402]
R95  4.7K  [0402]
R96  4.7K  [0402]
R97  4.7K  [0402]
R98  4.7K  [0402]
R99  4.7K  [0402]
R100  10  [0402]
R101  4.7K  [0402]
R102  4.7K  [0402]
R103  510  [0402]
R104  698  [0402]
R105  698  [0402]
R106  10K  [0402]
R107  10K  [0402]
R108  10  [0402]
R109  10K  [0402]
R110  10K  [0402]
R111  10K  [0402]
R112  10K  [0402]
R113  10K  [0402]
R114  10K  [0402]
R813  4.7K  [0402]
TP1  TP  [tp]
TP2  TP  [tp]
U19  PCA9546APW  [tssop_16]
U20  TXBN0304RSV  [qfn_p040_d040_b260x180_16]
U21  FXLP34P5X  [sc70_5]
U22  FXLP34P5X  [sc70_5]
sheet 08 EC&SD
C55  10pF  [0402]
C56  10pF  [0402]
C57  0.1uF  [0402]
C58  0.1uF  [0402]
C59  0.1uF  [0402]
C60  0.1uF  [0402]
C61  0.1uF  [0402]
C62  0.1uF  [0402]
C63  0.1uF  [0402]
C64  0.1uF  [0402]
C65  0.1uF  [0402]
C66  0.1uF  [0402]
C67  0.1uF  [0402]
C68  0.1uF  [0402]
R115  10  [0402]
R116  10  [0402]
R117  10  [0402]
R118  10  [0402]
R119  10  [0402]
R120  10  [0402]
R121  10  [0402]
R122  10  [0402]
R123  4.7K  [0402]
R124  4.7K  [0402]
R125  10  [0402]
R126  10  [0402]
R127  10  [0402]
R128  10  [0402]
R129  10  [0402]
R130  10  [0402]
R131  1.5K  [0402]
R132  4.7K  [0402]
R133  510  [0402o]
R134  270  [0402o]
R135  4.7K  [0402]
R136  4.7K  [0402]
R137  4.7K  [0402]
R138  1K  [0402]
R139  200  [0402]
R140  698  [0402]
TP3  TP  [tp]
TP4  TP  [tp]
TP5  TP  [tp]
TP6  TP  [tp]
TP7  TP  [tp]
TP8  TP  [tp]
TP9  TP  [tp]
TP10  TP  [tp]
TP11  TP  [tp]
TP12  TP  [tp]
TP13  TP  [tp]
TP14  TP  [tp]
U1  T1040  [bga_p080_780]  (sections A,B,C,D,E,F,G,H,I,J,K,L,M,N,O)
U23  74LVC1G66  [sc70_5]
U24  74LVC1G66  [sc70_5]
sheet 09 SerDes Mux
C69  0.01uF  [0402]
C70  0.01uF  [0402]
C71  0.01uF  [0402]
C72  0.01uF  [0402]
C73  0.01uF  [0402]
C74  0.01uF  [0402]
C75  0.01uF  [0402]
C76  0.01uF  [0402]
C77  0.01uF  [0402]
C78  0.01uF  [0402]
C79  0.01uF  [0402]
C80  0.01uF  [0402]
C81  0.01uF  [0402]
C82  0.01uF  [0402]
C83  0.01uF  [0402]
R141  4.7K  [0402]
R142  4.7K  [0402]
R143  4.7K  [0402]
U25  PI3PCIE3212  [qfn_p050_d040_b450x250_20_e3x1]
U26  PI3PCIE3212  [qfn_p050_d040_b450x250_20_e3x1]
U27  PI3PCIE3212  [qfn_p050_d040_b450x250_20_e3x1]
U28  PI3PCIE3212  [qfn_p050_d040_b450x250_20_e3x1]
U29  PI3PCIE3212  [qfn_p050_d040_b450x250_20_e3x1]

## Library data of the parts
C1 C2 C15 C21 C27 C33 C36 C38 = CAP: VOLTAGE: 6.3V
C3-C14 C16-C20 C23-C26 C28-C32 C34 C35 C37 C39-C43 C48-C54 C57-C68 C998 C999 C1059-C1062 C1071-C1074 = CAP: VOLTAGE: 16V
C22 = CAP: VOLTAGE: 10V
J1 = DDR3_DIMM: MPN: 78079-0053; TYPE: CON; Vendor: MOLEX
R1 R3 R104 R105 R139 R140 = RES: TOL: 1%
R2 R4-R7 R9-R12 R14-R48 R51 R52 R54-R103 R106-R138 R141-R143 R797-R804 R808-R810 R813 R864-R866 = RES: TOL: 5%
R13 R811 R812 = RES: BOM_IGNORE: DNP; TOL: 5%
SW1 SW2 = SWITCH_DIP_8: MPN: DHNF-08F-V; TYPE: CON; Vendor: DIPTRONICS
U2 = 74LVC16373: MPN: SN74LVC16373ADGGR; TYPE: IC; Vendor: TI
R49 = RES: BOM_IGNORE: VNIT; TOL: 5%
R50 = RES: BOM_IGNORE: VIT; TOL: 5%
U4 = FLASH-NOR-64Mx16: TYPE: IC; Vendor: Micron
U6 = FLASH-NAND-2: TYPE: IC; Vendor: Micron
U7 U11 U12 U18 U20 U98 U99 = TXBN0304RSV: MPN: TXBN0304RSVR; TYPE: IC; Vendor: TI
U8-U10 = 74LVC1G86: MPN: SN74LVC1G86DCKR; TYPE: IC; Vendor: TI
J2 = SD_CONN: MPN: 54-2119-9-R; TYPE: CON; Vendor: Astron
U13 = FLASH-SERIAL-SO16: TYPE: IC; Vendor: Micron
U15 = FLASH-SERIAL-SON: BOM_IGNORE: DNP; TYPE: IC; Vendor: Micron
U93 U94 = RClamp0524J: TYPE: IC; Vendor: Sentech
D1 = LED: MPN: 0603,Green
J3 = CONN_2X8: TYPE: HDR; Vendor: Samtec
Q1 Q2 = NMOS: MPN: IRLML6346TRPBF; TYPE: MOS; Vendor: IR
TP1-TP14 = TP
U19 = PCA9546A: TYPE: IC; Vendor: NXP
U21 U22 = FXLP34P5X: TYPE: IC; Vendor: FAIRCHILD
C55 C56 = CAP: BOM_IGNORE: DNP; VOLTAGE: 50V
U1 = T1040: TYPE: IC; Vendor: Freescale
U23 U24 = 74LVC1G66: MPN: SN74LVC1G66DCKR; TYPE: IC; Vendor: TI
C69-C83 = CAP: VOLTAGE: 25V
U25-U29 = PI3PCIE3212: MPN: PI3PCIE3212ZBE; TYPE: IC; Vendor: PERICOM

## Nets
1V8: R133.1 R134.1 ; also on sheet 12 21 31
1V35_SLP: C1.1 C2.1 C3.1 C4.1 C5.1 C6.1 C7.1 C8.1 C9.1 C10.1 C11.1 C12.1 C13.1 C14.1 C998.1 C999.1 J1.51(VDD) J1.54(VDD) J1.57(VDD) J1.60(VDD) J1.62(VDD) J1.65(VDD) J1.66(VDD) J1.69(VDD) J1.72(VDD) J1.75(VDD) J1.78(VDD) J1.170(VDD) J1.173(VDD) J1.176(VDD) J1.179(VDD) J1.182(VDD) J1.183(VDD) J1.186(VDD) J1.189(VDD) J1.191(VDD) J1.194(VDD) J1.197(VDD) R1.1 R2.1 R4.1 ; also on sheet 12 30 31
2V5: R138.2 ; also on sheet 12 16 17 18 19 20 31
2V5_SLP: C57.1 C58.1 R75.2 R76.2 R77.2 R78.2 R131.1 R132.1 U23.5(VCC) U24.5(VCC) ; also on sheet 12 15 30 31
3V3: C20.1 C27.1 C28.1 C29.1 C33.1 C34.1 C36.1 C37.1 C38.1 C39.1 C41.1 C43.1 C48.1 C49.1 C51.1 C69.1 C70.1 C71.1 C72.1 C73.1 C74.1 C75.1 C76.1 C77.1 C78.1 C79.1 C80.1 C81.1 C82.1 C83.1 C1060.1 C1062.1 C1072.1 C1074.1 J1.117(SA0) J1.236(VDDSPD) J2.4(VDD) R45.2 R46.2 R48.2 R51.2 R54.2 R55.2 R56.2 R57.2 R90.2 R91.2 R99.1 R107.1 R108.2 R109.2 R110.1 R111.1 R112.1 R113.1 R114.1 R142.1 R143.1 U4.43(VCC) U6.12(VCC) U6.37(VCC) U7.13(VCCB) U11.13(VCCB) U12.13(VCCB) U13.2(VCC) U15.8(VCC) U18.13(VCCB) U19.1(A0) U19.2(A1) U19.13(A2) U19.16(VDD) U20.16(VCCA) U22.5(VCC) U25.1(VDD) U25.6(VDD) U25.10(VDD) U26.1(VDD) U26.6(VDD) U26.10(VDD) U27.1(VDD) U27.6(VDD) U27.10(VDD) U28.1(VDD) U28.6(VDD) U28.10(VDD) U29.1(VDD) U29.6(VDD) U29.10(VDD) U98.13(VCCB) U99.13(VCCB) ; also on sheet 10 12 14 16 17 21 22 23 24 28 29 31 32
3V3_SLP: C54.1 U21.5(VCC) ; also on sheet 11 12 13 15 26 29 30 31 32
DVDD: Q1.1(G) Q2.1(G) R80.2 R86.2 R87.2 R88.2 R89.2 R92.2 R93.2 R95.2 R97.2 ; also on sheet 12 14 31
GND: C1.2 C2.2 C3.2 C4.2 C5.2 C6.2 C7.2 C8.2 C9.2 C10.2 C11.2 C12.2 C13.2 C14.2 C15.2 C16.2 C17.2 C18.2 C19.2 C20.2 C21.2 C22.2 C23.2 C24.2 C25.2 C26.2 C27.2 C28.2 C29.2 C30.2 C31.2 C32.2 C33.2 C34.2 C35.2 C36.2 C37.2 C38.2 C39.2 C40.2 C41.2 C42.2 C43.2 C48.2 C49.2 C50.2 C51.2 C52.2 C53.2 C54.2 C55.1 C56.2 C57.2 C58.2 C69.2 C70.2 C71.2 C72.2 C73.2 C74.2 C75.2 C76.2 C77.2 C78.2 C79.2 C80.2 C81.2 C82.2 C83.2 C998.2 C999.2 C1059.2 C1060.2 C1061.2 C1062.2 C1071.2 C1072.2 C1073.2 C1074.2 D1.1 J1.2(VSS) J1.5(VSS) J1.8(VSS) J1.11(VSS) J1.14(VSS) J1.17(VSS) J1.20(VSS) J1.23(VSS) J1.26(VSS) J1.29(VSS) J1.32(VSS) J1.35(VSS) J1.38(VSS) J1.41(VSS) J1.44(VSS) J1.47(VSS) J1.80(VSS) J1.83(VSS) J1.86(VSS) J1.89(VSS) J1.92(VSS) J1.95(VSS) J1.98(VSS) J1.101(VSS) J1.104(VSS) J1.107(VSS) J1.110(VSS) J1.113(VSS) J1.116(VSS) J1.119(SA2) J1.121(VSS) J1.124(VSS) J1.127(VSS) J1.130(VSS) J1.133(VSS) J1.136(VSS) J1.139(VSS) J1.142(VSS) J1.145(VSS) J1.148(VSS) J1.151(VSS) J1.154(VSS) J1.157(VSS) J1.160(VSS) J1.163(VSS) J1.166(VSS) J1.199(VSS) J1.202(VSS) J1.205(VSS) J1.208(VSS) J1.211(VSS) J1.214(VSS) J1.217(VSS) J1.220(VSS) J1.223(VSS) J1.226(VSS) J1.229(VSS) J1.232(VSS) J1.235(VSS) J1.237(SA1) J1.239(VSS) J2.3(VSS) J2.6(VSS) J2.12(COM1) J2.13(COM2) J3.12 J3.16 R3.1 R13.1 R17.2 R19.2 R21.2 R23.2 R25.2 R27.2 R29.2 R31.2 R33.2 R34.2 R35.2 R36.2 R37.2 R38.2 R39.2 R40.2 R52.2 R104.1 R105.1 R106.1 R123.1 R124.2 R135.1 R136.1 R137.1 R141.1 R809.1 R810.1 R811.2 R812.2 U1.AC1(EC1_COL) U1.AC2(EC1_RX_ER) U2.1(~{OE1}) U2.4(GND) U2.10(GND) U2.15(GND) U2.21(GND) U2.24(~{OE2}) U2.26(2D8) U2.27(2D7) U2.28(GND) U2.29(2D6) U2.30(2D5) U2.32(2D4) U2.34(GND) U2.39(GND) U2.45(GND) U4.33(GND) U4.52(GND) U6.13(GND) U6.36(GND) U7.6(GND) U7.7(GND) U8.3(GND) U9.3(GND) U10.3(GND) U11.6(GND) U11.7(GND) U12.6(GND) U12.7(GND) U12.8(~{OE}) U13.10(GND) U15.4(GND) U15.9(EPAD) U18.6(GND) U18.7(GND) U18.8(~{OE}) U19.8(VSS) U20.6(GND) U20.7(GND) U20.8(~{OE}) U21.3(GND) U22.3(GND) U23.3(GND) U24.3(GND) U25.5(GND) U25.9(SEL) U25.11(GND) U25.20(GND) U25.21(EPAD) U26.2(PD) U26.5(GND) U26.11(GND) U26.20(GND) U26.21(EPAD) U27.2(PD) U27.5(GND) U27.11(GND) U27.20(GND) U27.21(EPAD) U28.2(PD) U28.5(GND) U28.11(GND) U28.20(GND) U28.21(EPAD) U29.2(PD) U29.5(GND) U29.11(GND) U29.20(GND) U29.21(EPAD) U93.9 U94.9 U98.6(GND) U98.7(GND) U99.6(GND) U99.7(GND) ; also on sheet 10 11 12 13 14 15 16 17 18 19 20 21 22 23 24 25 26 27 28 29 30 31 32 33
SVDD: R139.1 ; also on sheet 12
ASLEEP: R101.1 U1.B2(ASLEEP) U21.2(A)
CFG_VBANK0: U10.2(I1) ; also on sheet 26
CFG_VBANK1: U9.2(I1) ; also on sheet 26
CFG_VBANK2: U8.2(I1) ; also on sheet 26
CKSTP_OUT_N: R102.1 U1.F18(CKSTP_OUT_B) U22.2(A)
COP_CKSTP_OUT_N: J3.15 U22.4(O)
COP_HRESET_N: J3.13 R107.2 ; also on sheet 26
COP_SRESET_N: J3.11 R110.2 ; also on sheet 26
COP_TCK: J3.7 R113.2 U20.3(A3)
COP_TDI: J3.3 R111.2 U20.1(A1)
COP_TDO: J3.1 U20.2(A2)
COP_TMS: J3.9 R114.2 U20.4(A4)
COP_TRST_N: J3.4 R109.1 ; also on sheet 26
CPLD_INT1_N: R69.1 U1.F7(IRQ00) ; also on sheet 26
CPLD_INT2_N: R70.1 U1.D3(IRQ01) ; also on sheet 26
DDR_DQ0: J1.3(DQ0) U1.C21(D1_MDQ00)
DDR_DQ1: J1.4(DQ1) U1.A22(D1_MDQ01)
DDR_DQ2: J1.9(DQ2) U1.A26(D1_MDQ02)
DDR_DQ3: J1.10(DQ3) U1.B26(D1_MDQ03)
DDR_DQ4: J1.122(DQ4) U1.B21(D1_MDQ04)
DDR_DQ5: J1.123(DQ5) U1.A21(D1_MDQ05)
DDR_DQ6: J1.128(DQ6) U1.B24(D1_MDQ06)
DDR_DQ7: J1.129(DQ7) U1.A25(D1_MDQ07)
DDR_DQ8: J1.12(DQ8) U1.C23(D1_MDQ08)
DDR_DQ9: J1.13(DQ9) U1.C24(D1_MDQ09)
DDR_DQ10: J1.18(DQ10) U1.F25(D1_MDQ10)
DDR_DQ11: J1.19(DQ11) U1.F26(D1_MDQ11)
DDR_DQ12: J1.131(DQ12) U1.D22(D1_MDQ12)
DDR_DQ13: J1.132(DQ13) U1.D23(D1_MDQ13)
DDR_DQ14: J1.137(DQ14) U1.B27(D1_MDQ14)
DDR_DQ15: J1.138(DQ15) U1.E25(D1_MDQ15)
DDR_DQ16: J1.21(DQ16) U1.E23(D1_MDQ16)
DDR_DQ17: J1.22(DQ17) U1.E24(D1_MDQ17)
DDR_DQ18: J1.27(DQ18) U1.J23(D1_MDQ18)
DDR_DQ19: J1.28(DQ19) U1.K23(D1_MDQ19)
DDR_DQ20: J1.140(DQ20) U1.F22(D1_MDQ20)
DDR_DQ21: J1.141(DQ21) U1.H22(D1_MDQ21)
DDR_DQ22: J1.146(DQ22) U1.H23(D1_MDQ22)
DDR_DQ23: J1.147(DQ23) U1.J24(D1_MDQ23)
DDR_DQ24: J1.30(DQ24) U1.H26(D1_MDQ24)
DDR_DQ25: J1.31(DQ25) U1.J25(D1_MDQ25)
DDR_DQ26: J1.36(DQ26) U1.P26(D1_MDQ26)
DDR_DQ27: J1.37(DQ27) U1.N25(D1_MDQ27)
DDR_DQ28: J1.149(DQ28) U1.G25(D1_MDQ28)
DDR_DQ29: J1.150(DQ29) U1.H25(D1_MDQ29)
DDR_DQ30: J1.155(DQ30) U1.M26(D1_MDQ30)
DDR_DQ31: J1.156(DQ31) U1.M25(D1_MDQ31)
DDR_DQ32: J1.81(DQ32) U1.T25(D1_MDQ32)
DDR_DQ33: J1.82(DQ33) U1.U25(D1_MDQ33)
DDR_DQ34: J1.87(DQ34) U1.AA26(D1_MDQ34)
DDR_DQ35: J1.88(DQ35) U1.AA25(D1_MDQ35)
DDR_DQ36: J1.200(DQ36) U1.P25(D1_MDQ36)
DDR_DQ37: J1.201(DQ37) U1.R25(D1_MDQ37)
DDR_DQ38: J1.206(DQ38) U1.W26(D1_MDQ38)
DDR_DQ39: J1.207(DQ39) U1.Y25(D1_MDQ39)
DDR_DQ40: J1.90(DQ40) U1.V24(D1_MDQ40)
DDR_DQ41: J1.91(DQ41) U1.W23(D1_MDQ41)
DDR_DQ42: J1.96(DQ42) U1.AA22(D1_MDQ42)
DDR_DQ43: J1.97(DQ43) U1.AC22(D1_MDQ43)
DDR_DQ44: J1.209(DQ44) U1.W22(D1_MDQ44)
DDR_DQ45: J1.210(DQ45) U1.V23(D1_MDQ45)
DDR_DQ46: J1.215(DQ46) U1.AB24(D1_MDQ46)
DDR_DQ47: J1.216(DQ47) U1.AB23(D1_MDQ47)
DDR_DQ48: J1.99(DQ48) U1.AD26(D1_MDQ48)
DDR_DQ49: J1.100(DQ49) U1.AD25(D1_MDQ49)
DDR_DQ50: J1.105(DQ50) U1.AD23(D1_MDQ50)
DDR_DQ51: J1.106(DQ51) U1.AE22(D1_MDQ51)
DDR_DQ52: J1.218(DQ52) U1.AB25(D1_MDQ52)
DDR_DQ53: J1.219(DQ53) U1.AC25(D1_MDQ53)
DDR_DQ54: J1.224(DQ54) U1.AC23(D1_MDQ54)
DDR_DQ55: J1.225(DQ55) U1.AE23(D1_MDQ55)
DDR_DQ56: J1.108(DQ56) U1.AG25(D1_MDQ56)
DDR_DQ57: J1.109(DQ57) U1.AH25(D1_MDQ57)
DDR_DQ58: J1.114(DQ58) U1.AH22(D1_MDQ58)
DDR_DQ59: J1.115(DQ59) U1.AF22(D1_MDQ59)
DDR_DQ60: J1.227(DQ60) U1.AF26(D1_MDQ60)
DDR_DQ61: J1.228(DQ61) U1.AH26(D1_MDQ61)
DDR_DQ62: J1.233(DQ62) U1.AH23(D1_MDQ62)
DDR_DQ63: J1.234(DQ63) U1.AF23(D1_MDQ63)
DDR_ECC0: J1.39(CB0) U1.L24(D1_MECC0)
DDR_ECC1: J1.40(CB1) U1.N23(D1_MECC1)
DDR_ECC2: J1.45(CB2) U1.T23(D1_MECC2)
DDR_ECC3: J1.46(CB3) U1.U23(D1_MECC3)
DDR_ECC4: J1.158(CB4) U1.L23(D1_MECC4)
DDR_ECC5: J1.159(CB5) U1.M23(D1_MECC5)
DDR_ECC6: J1.164(CB6) U1.R24(D1_MECC6)
DDR_ECC7: J1.165(CB7) U1.T24(D1_MECC7)
DDR_MA0: J1.188(A0) U1.V28(D1_MA00)
DDR_MA1: J1.181(A1) U1.N28(D1_MA01)
DDR_MA2: J1.61(A2) U1.N27(D1_MA02)
DDR_MA3: J1.180(A3) U1.M28(D1_MA03)
DDR_MA4: J1.59(A4) U1.L27(D1_MA04)
DDR_MA5: J1.58(A5) U1.L28(D1_MA05)
DDR_MA6: J1.178(A6) U1.K28(D1_MA06)
DDR_MA7: J1.56(A7) U1.J28(D1_MA07)
DDR_MA8: J1.177(A8) U1.J27(D1_MA08)
DDR_MA9: J1.175(A9) U1.G27(D1_MA09)
DDR_MA10: J1.70(A10/AP) U1.Y27(D1_MA10)
DDR_MA11: J1.55(A11) U1.H28(D1_MA11)
DDR_MA12: J1.174(A12/~{BC}) U1.G28(D1_MA12)
DDR_MA13: J1.196(A13) U1.AE28(D1_MA13)
DDR_MA14: J1.172(A14) U1.E27(D1_MA14)
DDR_MA15: J1.171(A15) U1.D28(D1_MA15)
DDR_MAPAR_ERR: J1.53(~{ERROUT}/NC) R4.2 U1.F28(D1_MAPAR_ERR_B)
DDR_MAPAR_OUT: J1.68(PARIN/NC) U1.V27(D1_MAPAR_OUT)
DDR_MBA0: J1.71(BA0) U1.Y28(D1_MBA0)
DDR_MBA1: J1.190(BA1) U1.W28(D1_MBA1)
DDR_MBA2: J1.52(BA2) U1.E28(D1_MBA2)
DDR_MCAS_N: J1.74(~{CAS}) U1.AC28(D1_MCAS_B)
DDR_MCK0_N: J1.185(~{CK0}) U1.T28(D1_MCK0_B)
DDR_MCK0_P: J1.184(CK0) U1.T27(D1_MCK0)
DDR_MCK1_N: J1.64(~{CK1}) U1.R28(D1_MCK1_B)
DDR_MCK1_P: J1.63(CK1) U1.R27(D1_MCK1)
DDR_MCKE0: J1.50(CKE0) U1.C27(D1_MCKE0) ; also on sheet 31
DDR_MCKE1: J1.169(CKE1) U1.C28(D1_MCKE1) ; also on sheet 31
DDR_MCS0_N: J1.193(~{S0}) U1.AB28(D1_MCS0_B)
DDR_MCS1_N: J1.76(~{S1}) U1.AC27(D1_MCS1_B)
DDR_MCS2_N: J1.79(~{S2}/NC) U1.AG27(D1_MCS2_B)
DDR_MCS3_N: J1.198(~{S3}/NC) U1.AF28(D1_MCS3_B)
DDR_MDM0: J1.125(DM0/DQS9) U1.B22(D1_MDM0)
DDR_MDM1: J1.134(DM1/DQS10) U1.C25(D1_MDM1)
DDR_MDM2: J1.143(DM2/DQS11) U1.F23(D1_MDM2)
DDR_MDM3: J1.152(DM3/DQS12) U1.K26(D1_MDM3)
DDR_MDM4: J1.203(DM4/DQS13) U1.U26(D1_MDM4)
DDR_MDM5: J1.212(DM5/DQS14) U1.Y24(D1_MDM5)
DDR_MDM6: J1.221(DM6/DQS15) U1.AD24(D1_MDM6)
DDR_MDM7: J1.230(DM7/DQS16) U1.AF24(D1_MDM7)
DDR_MDM8: J1.161(DM8/DQS17) U1.N24(D1_MDM8)
DDR_MDQS0_N: J1.6(~{DQS0}) U1.A23(D1_MDQS0_B)
DDR_MDQS0_P: J1.7(DQS0) U1.A24(D1_MDQS0)
DDR_MDQS1_N: J1.15(~{DQS1}) U1.D25(D1_MDQS1_B)
DDR_MDQS1_P: J1.16(DQS1) U1.D26(D1_MDQS1)
DDR_MDQS2_N: J1.24(~{DQS2}) U1.G23(D1_MDQS2_B)
DDR_MDQS2_P: J1.25(DQS2) U1.G24(D1_MDQS2)
DDR_MDQS3_N: J1.33(~{DQS3}) U1.K25(D1_MDQS3_B)
DDR_MDQS3_P: J1.34(DQS3) U1.L25(D1_MDQS3)
DDR_MDQS4_N: J1.84(~{DQS4}) U1.V25(D1_MDQS4_B)
DDR_MDQS4_P: J1.85(DQS4) U1.W25(D1_MDQS4)
DDR_MDQS5_N: J1.93(~{DQS5}) U1.Y23(D1_MDQS5_B)
DDR_MDQS5_P: J1.94(DQS5) U1.AA23(D1_MDQS5)
DDR_MDQS6_N: J1.102(~{DQS6}) U1.AF25(D1_MDQS6_B)
DDR_MDQS6_P: J1.103(DQS6) U1.AE25(D1_MDQS6)
DDR_MDQS7_N: J1.111(~{DQS7}) U1.AH24(D1_MDQS7_B)
DDR_MDQS7_P: J1.112(DQS7) U1.AG24(D1_MDQS7)
DDR_MDQS8_N: J1.42(~{DQS8}) U1.P23(D1_MDQS8_B)
DDR_MDQS8_P: J1.43(DQS8) U1.R23(D1_MDQS8)
DDR_MODT0: J1.195(ODT0) U1.AD28(D1_MODT0)
DDR_MODT1: J1.77(ODT1) U1.AE27(D1_MODT1)
DDR_MRAS_N: J1.192(~{RAS}) U1.AA28(D1_MRAS_B)
DDR_MWE_N: J1.73(~{WE}) U1.AB27(D1_MWE_B)
DDR_REFCLK: U1.J21(DDRCLK) ; also on sheet 27
DDR_RST_N: J1.168(~{RESET}) R2.2 ; also on sheet 26
EC1_GTXCLK: R127.1 ; also on sheet 15
EC1_INT_N: R75.1 U1.AB4(IRQ06) ; also on sheet 15
EC1_PME_N: R76.1 U1.AD5(IRQ07) ; also on sheet 15
EC1_REFCLK: U1.AG3(EC1_GTX_CLK125) ; also on sheet 15
EC1_RXCLK: U1.AD1(EC1_RX_CLK) ; also on sheet 15
EC1_RXCTL: U1.AG2(EC1_RX_CTL) ; also on sheet 15
EC1_RXD0: U1.AF2(EC1_RXD0) ; also on sheet 15
EC1_RXD1: U1.AF1(EC1_RXD1) ; also on sheet 15
EC1_RXD2: U1.AE1(EC1_RXD2) ; also on sheet 15
EC1_RXD3: U1.AD2(EC1_RXD3) ; also on sheet 15
EC1_TXCTL: R125.1 ; also on sheet 15
EC1_TXD0: R115.1 ; also on sheet 15
EC1_TXD1: R116.1 ; also on sheet 15
EC1_TXD2: R119.1 ; also on sheet 15
EC1_TXD3: R121.1 ; also on sheet 15
EC2_GTXCLK: R128.2 ; also on sheet 16
EC2_INT_N: R79.1 U1.L4(IRQ10) ; also on sheet 16
EC2_PME_N: R80.1 U1.U3(IRQ11) ; also on sheet 16
EC2_REFCLK: U1.AC6(EC2_GTX_CLK125) ; also on sheet 16
EC2_RXCLK: U1.AH5(EC2_RX_CLK) ; also on sheet 16
EC2_RXCTL: U1.AG8(EC2_RX_CTL) ; also on sheet 16
EC2_RXD0: U1.AH8(EC2_RXD0) ; also on sheet 16
EC2_RXD1: U1.AG7(EC2_RXD1) ; also on sheet 16
EC2_RXD2: U1.AH7(EC2_RXD2) ; also on sheet 16
EC2_RXD3: U1.AH6(EC2_RXD3) ; also on sheet 16
EC2_TXCTL: R126.2 ; also on sheet 16
EC2_TXD0: R117.2 ; also on sheet 16
EC2_TXD1: R118.2 ; also on sheet 16
EC2_TXD2: R120.2 ; also on sheet 16
EC2_TXD3: R122.2 ; also on sheet 16
EMI1_MDC: U23.2(B) ; also on sheet 16 17 18 19
EMI1_MDC_SLP: R129.1 R132.2 U23.1(A) ; also on sheet 15
EMI1_MDIO: U24.2(B) ; also on sheet 16 17 18 19
EMI1_MDIO_SLP: R131.2 U1.AH4(EMI1_MDIO) U24.1(A) ; also on sheet 15
EMI2_MDC: R130.2 R134.2 ; also on sheet 21
EMI2_MDIO: R133.2 U1.M6(EMI2_MDIO) ; also on sheet 21
EVDD: R60.2 R62.2 R63.2 R64.2 R67.2 R68.2 ; also on sheet 12 31
EVT_BRD_ISO: R81.1 U1.A3(IRQ_OUT_B) ; also on sheet 26
EVT_PWR_EN: R85.1 U1.C1(EVT2_B) ; also on sheet 26
EVT_PWR_OK: R813.1 U1.C2(EVT3_B) ; also on sheet 26
GPIO_CKE_ISO: R78.1 U1.AC5(IRQ09) ; also on sheet 26
HRESET_N: R96.2 U1.E8(HRESET_B) ; also on sheet 26
I2C1_SCL: J1.118(SCL) Q1.3(D) R91.1 ; also on sheet 14 29
I2C1_SDA: J1.238(SDA) Q2.3(D) R90.1 ; also on sheet 14 29
I2C2_MPEX1_SCL: U19.5(SC0) ; also on sheet 22
I2C2_MPEX1_SDA: U19.4(SD0) ; also on sheet 22
I2C2_MPEX2_SCL: U19.7(SC1) ; also on sheet 22
I2C2_MPEX2_SDA: U19.6(SD1) ; also on sheet 22
I2C2_PEX_SCL: U19.12(SC3) ; also on sheet 22
I2C2_PEX_SDA: U19.11(SD3) ; also on sheet 22
I2C2_SFPP_SCL: U19.10(SC2) ; also on sheet 21
I2C2_SFPP_SDA: U19.9(SD2) ; also on sheet 21
IFC_A5: R14.2 U10.1(I0)
IFC_A6: R15.2 U9.1(I0)
IFC_A7: R16.2 U8.1(I0)
IFC_A8: R18.2 U4.2(A22)
IFC_A9: R20.2 U4.15(A21)
IFC_A10: R22.2 U4.12(A20)
IFC_A11: R24.2 U4.11(A19)
IFC_A12: R26.2 U4.18(A18)
IFC_A13: R28.2 U4.19(A17)
IFC_A14: R30.2 U4.54(A16)
IFC_A15: R32.2 U4.3(A15)
IFC_A16: R797.2 SW2.5 U1.C5(IFC_A16) U4.4(A14) ; also on sheet 26
IFC_A17: R798.2 SW2.6 U1.C6(IFC_A17) U4.5(A13) ; also on sheet 26
IFC_A18: R799.2 SW2.3 U1.D7(IFC_A18) U4.6(A12)
IFC_A19: R800.2 SW2.4 U1.C7(IFC_A19) U4.7(A11)
IFC_A20: R13.2 R864.2 U1.D8(IFC_A20) U4.8(A10)
IFC_A21: SW2.7 U1.C8(IFC_A21) U4.9(A9)
IFC_A22: U1.D9(IFC_A22) U4.10(A8)
IFC_A23: R810.2 U1.C9(IFC_A23) U4.20(A7)
IFC_A24: R809.2 U1.D10(IFC_A24) U4.21(A6)
IFC_A25: U1.C10(IFC_A25) U4.22(A5)
IFC_A26: U1.E11(IFC_A26) U4.23(A4)
IFC_A27: U1.C11(IFC_A27) U4.24(A3) ; also on sheet 26
IFC_A28: U1.D11(IFC_A28) U4.25(A2) ; also on sheet 26
IFC_A29: U1.C12(IFC_A29) U4.26(A1) ; also on sheet 26
IFC_A30: U1.D12(IFC_A30) U4.31(A0) ; also on sheet 26
IFC_A31: U1.E12(IFC_A31) ; also on sheet 26
IFC_AD0: U1.A4(IFC_AD00) U4.51(DQ15/A-1) U99.4(A4) ; also on sheet 26
IFC_AD1: U1.B5(IFC_AD01) U4.49(DQ14) U99.3(A3) ; also on sheet 26
IFC_AD2: U1.A5(IFC_AD02) U4.47(DQ13) U99.2(A2) ; also on sheet 26
IFC_AD3: U1.B6(IFC_AD03) U4.45(DQ12) U99.1(A1) ; also on sheet 26
IFC_AD4: U1.A6(IFC_AD04) U4.42(DQ11) U98.4(A4) ; also on sheet 26
IFC_AD5: U1.A7(IFC_AD05) U2.47(1D1) U4.40(DQ10) U98.3(A3) ; also on sheet 26
IFC_AD6: U1.B8(IFC_AD06) U2.46(1D2) U4.38(DQ9) U98.2(A2) ; also on sheet 26
IFC_AD7: U1.A8(IFC_AD07) U2.44(1D3) U4.36(DQ8) U98.1(A1) ; also on sheet 26
IFC_AD8: SW1.1 U1.B9(IFC_AD08) U2.43(1D4) U4.50(DQ7) ; also on sheet 26
IFC_AD9: SW1.2 U1.A9(IFC_AD09) U2.41(1D5) U4.48(DQ6) ; also on sheet 26
IFC_AD10: SW1.3 U1.A10(IFC_AD10) U2.40(1D6) U4.46(DQ5) ; also on sheet 26
IFC_AD11: SW1.4 U1.B11(IFC_AD11) U2.38(1D7) U4.44(DQ4) ; also on sheet 26
IFC_AD12: SW1.5 U1.A11(IFC_AD12) U2.37(1D8) U4.41(DQ3) ; also on sheet 26
IFC_AD13: SW1.6 U1.B12(IFC_AD13) U2.36(2D1) U4.39(DQ2) ; also on sheet 26
IFC_AD14: SW1.7 U1.A12(IFC_AD14) U2.35(2D2) U4.37(DQ1) ; also on sheet 26
IFC_AD15: SW1.8 U1.A13(IFC_AD15) U2.33(2D3) U4.35(DQ0) ; also on sheet 26
IFC_AVD: R49.1 R801.1 SW2.8 U1.D17(IFC_AVD) U2.25(LE2) U2.48(LE1)
IFC_CLE: SW2.1 U1.F16(IFC_CLE) U7.3(A3) ; also on sheet 26
IFC_CLK: R12.2 ; also on sheet 26
IFC_CS0_N: R11.1 U1.C13(IFC_CS0_B) ; also on sheet 26
IFC_CS1_N: R10.1 U1.E15(IFC_CS1_B) ; also on sheet 26
IFC_CS2_N: R9.1 U1.D16(IFC_CS2_B) ; also on sheet 26
IFC_LATCH_N: R808.2 U7.8(~{OE}) U11.8(~{OE}) U98.8(~{OE}) U99.8(~{OE}) ; also on sheet 26
IFC_NDWE_N: U1.D14(IFC_NDDDR_CLK) U11.1(A1)
IFC_OE_N: R803.1 U1.D15(IFC_OE_B) U4.34(~{OE}) U7.1(A1) ; also on sheet 26
IFC_PAR1: R50.1 R812.1 U1.C14(IFC_PAR1)
IFC_RB0_N: R7.1 U1.B15(IFC_RB0_B) ; also on sheet 26
IFC_RB1_N: R6.1 U1.A15(IFC_RB1_B) ; also on sheet 26
IFC_TE: SW2.2 U1.B14(IFC_TE)
IFC_VA5: U4.55(A25) U10.4(O)
IFC_VA6: U4.56(A24) U9.4(O)
IFC_VA7: U4.1(A23) U8.4(O)
IFC_WE_N: R804.1 U1.D13(IFC_WE0_B) U4.13(~{WE}) ; also on sheet 26
IFC_WP_N: R802.1 U1.F17(IFC_WP0_B) U11.2(A2) ; also on sheet 26
JTAG_TCK: U1.E18(TCK) U20.10(B3)
JTAG_TDI: U1.A18(TDI) U20.12(B1)
JTAG_TDO: U1.C18(TDO) U20.11(B2)
JTAG_TMS: U1.B18(TMS) U20.9(B4)
JTAG_TRST_N: U1.D19(TRST_B) ; also on sheet 26
LP_TMPDET_N: U1.R6(LP_TMP_DETECT_B) ; also on sheet 32
MPEX1_RX_N: U26.15(C0+) ; also on sheet 22
MPEX1_RX_P: U26.14(C0-) ; also on sheet 22
MPEX1_TX_N: U26.13(C1+) ; also on sheet 22
MPEX1_TX_P: U26.12(C1-) ; also on sheet 22
MPEX2_RX_N: U28.15(C0+) ; also on sheet 22
MPEX2_RX_P: U28.14(C0-) ; also on sheet 22
MPEX2_TX_N: U28.13(C1+) ; also on sheet 22
MPEX2_TX_P: U28.12(C1-) ; also on sheet 22
MVREF: C18.1 C19.1 C21.1 C22.1 J1.1(VREFDQ) J1.67(VREFCA) U1.F20(D1_MVREF) ; also on sheet 31
NAND_CS_N: U7.2(A2) ; also on sheet 26
NAND_IO0: U6.29(IO0) U98.12(B1)
NAND_IO1: U6.30(IO1) U98.11(B2)
NAND_IO2: U6.31(IO2) U98.10(B3)
NAND_IO3: U6.32(IO3) U98.9(B4)
NAND_IO4: U6.41(IO4) U99.12(B1)
NAND_IO5: U6.42(IO5) U99.11(B2)
NAND_IO6: U6.43(IO6) U99.10(B3)
NAND_IO7: U6.44(IO7) U99.9(B4)
NAND_RB_N: R48.1 U6.7(R/~{B1}) ; also on sheet 26
NOR_CS_N: R43.1 U4.32(~{CE}) ; also on sheet 26
NOR_RST_N: R47.1 U4.14(~{RESET}) ; also on sheet 26
OVDD: C23.1 C24.1 C25.1 C26.1 C30.1 C31.1 C32.1 C35.1 C40.1 C42.1 C50.1 C53.1 C1059.1 C1061.1 C1071.1 C1073.1 R5.2 R6.2 R7.2 R9.2 R10.2 R11.2 R41.2 R42.2 R43.2 R44.2 R47.2 R65.2 R66.2 R79.2 R81.2 R82.2 R102.2 R797.1 R798.1 R799.1 R800.1 R801.2 R802.2 R803.2 R804.2 R808.1 R864.1 U2.7(VCC) U2.18(VCC) U2.31(VCC) U2.42(VCC) U4.29(VIO) U7.16(VCCA) U8.5(VCC) U9.5(VCC) U10.5(VCC) U11.16(VCCA) U12.16(VCCA) U18.16(VCCA) U20.13(VCCB) U22.1(VCC1) U98.16(VCCA) U99.16(VCCA) ; also on sheet 12 13 26 27
OVDD_SLP: C52.1 R69.2 R70.2 R71.2 R72.2 R73.2 R74.2 R83.2 R84.2 R85.2 R94.1 R96.1 R98.1 R101.2 R813.2 U21.1(VCC1) ; also on sheet 11 12 13 26 27
PEX2_SEL_N: R142.2 U26.9(SEL) ; also on sheet 26
PEX4_SEL_N: R143.2 U28.9(SEL) U29.9(SEL) ; also on sheet 26
PEX_RX0_N: U1.AG16(SD1_RX4_N) ; also on sheet 22
PEX_RX0_P: U1.AH16(SD1_RX4_P) ; also on sheet 22
PEX_RX1_N: U26.19(B0+) ; also on sheet 22
PEX_RX1_P: U26.18(B0-) ; also on sheet 22
PEX_RX2_N: U28.19(B0+) ; also on sheet 22
PEX_RX2_P: U28.18(B0-) ; also on sheet 22
PEX_RX3_N: U29.19(B0+) ; also on sheet 22
PEX_RX3_P: U29.18(B0-) ; also on sheet 22
PEX_TX0_N: U1.AE16(SD1_TX4_N) ; also on sheet 22
PEX_TX0_P: U1.AD16(SD1_TX4_P) ; also on sheet 22
PEX_TX1_N: U26.17(B1+) ; also on sheet 22
PEX_TX1_P: U26.16(B1-) ; also on sheet 22
PEX_TX2_N: U28.17(B1+) ; also on sheet 22
PEX_TX2_P: U28.16(B1-) ; also on sheet 22
PEX_TX3_N: U29.17(B1+) ; also on sheet 22
PEX_TX3_P: U29.16(B1-) ; also on sheet 22
PORESET_N: R94.2 U1.F13(PORESET_B) ; also on sheet 26
POTS_TDM_CLK: R100.1 ; also on sheet 23 24
POTS_TDM_FS: U1.U5(DMA1_DACK0_B) ; also on sheet 23 24
POTS_TDM_RXD: U1.V5(DMA2_DREQ0_B) ; also on sheet 23 24
POTS_TDM_TXD: U1.P5(DMA1_DREQ0_B) ; also on sheet 23 24
POTSA_SPI_CS_N: U18.10(B3) ; also on sheet 23
POTSB_SPI_CS_N: U18.11(B2) ; also on sheet 24
PROC_SPI_CLK: R59.2 U12.3(A3)
PROC_SPI_CS0_N: U1.M1(SPI_CS0_B) U12.4(A4)
PROC_SPI_CS1_N: U1.M2(SPI_CS1_B) U18.3(A3)
PROC_SPI_CS2_N: U1.M3(SPI_CS2_B) U18.2(A2)
PROC_SPI_CS3_N: U1.N3(SPI_CS3_B) U18.1(A1)
PROC_SPI_MISO: U1.P1(SPI_MISO) U12.1(A1)
PROC_SPI_MOSI: U1.P2(SPI_MOSI) U12.2(A2)
PROC_UART1_CTS_N: U1.Y2(UART1_CTS_B) ; also on sheet 14
PROC_UART1_RTS_N: U1.Y1(UART1_RTS_B) ; also on sheet 14
PROC_UART1_RXD: U1.AA1(UART1_SIN) ; also on sheet 14
PROC_UART1_TXD: U1.AA2(UART1_SOUT) ; also on sheet 14
PROC_UART2_CTS_N: U1.Y4(UART2_CTS_B) ; also on sheet 14
PROC_UART2_RTS_N: U1.V4(UART2_RTS_B) ; also on sheet 14
PROC_UART2_RXD: U1.W4(UART2_SIN) ; also on sheet 14
PROC_UART2_TXD: U1.AA4(UART2_SOUT) ; also on sheet 14
QSGMII1_RX_N: U27.19(B0+) ; also on sheet 18
QSGMII1_RX_P: U27.18(B0-) ; also on sheet 18
QSGMII1_TX_N: U27.17(B1+) ; also on sheet 18
QSGMII1_TX_P: U27.16(B1-) ; also on sheet 18
QSGMII2_RX_N: C66.1 ; also on sheet 19
QSGMII2_RX_P: C62.1 ; also on sheet 19
QSGMII2_TX_N: U1.AE14(SD1_TX3_N) ; also on sheet 19
QSGMII2_TX_P: U1.AD14(SD1_TX3_P) ; also on sheet 19
RESET_REQ_N: R98.2 U1.B3(RESET_REQ_B) ; also on sheet 26
SATA_RX_N: U29.15(C0+) ; also on sheet 22
SATA_RX_P: U29.14(C0-) ; also on sheet 22
SATA_TX_N: U29.13(C1+) ; also on sheet 22
SATA_TX_P: U29.12(C1-) ; also on sheet 22
SD_REFCLK1_N: C68.1 ; also on sheet 28
SD_REFCLK1_P: C67.1 ; also on sheet 28
SD_REFCLK2_N: U1.AA18(SD1_REF_CLK2_N) ; also on sheet 27
SD_REFCLK2_P: U1.AB18(SD1_REF_CLK2_P) ; also on sheet 27
SD_RX1_N: C64.1 U25.8(A1-)
SD_RX1_P: C63.1 U25.7(A1+)
SD_RX2_N: C61.1 U27.3(A0+)
SD_RX2_P: C65.1 U27.4(A0-)
SD_RX5_N: U1.AG17(SD1_RX5_N) U26.3(A0+)
SD_RX5_P: U1.AH17(SD1_RX5_P) U26.4(A0-)
SD_RX6_N: U1.AG19(SD1_RX6_N) U28.3(A0+)
SD_RX6_P: U1.AH19(SD1_RX6_P) U28.4(A0-)
SD_RX7_N: U1.AG20(SD1_RX7_N) U29.3(A0+)
SD_RX7_P: U1.AH20(SD1_RX7_P) U29.4(A0-)
SD_TX1_N: U1.AE11(SD1_TX1_N) U25.4(A0-)
SD_TX1_P: U1.AD11(SD1_TX1_P) U25.3(A0+)
SD_TX2_N: U1.AE13(SD1_TX2_N) U27.7(A1+)
SD_TX2_P: U1.AD13(SD1_TX2_P) U27.8(A1-)
SD_TX5_N: U1.AE17(SD1_TX5_N) U26.7(A1+)
SD_TX5_P: U1.AD17(SD1_TX5_P) U26.8(A1-)
SD_TX6_N: U1.AE19(SD1_TX6_N) U28.7(A1+)
SD_TX6_P: U1.AD19(SD1_TX6_P) U28.8(A1-)
SD_TX7_N: U1.AE20(SD1_TX7_N) U29.7(A1+)
SD_TX7_P: U1.AD20(SD1_TX7_P) U29.8(A1-)
SDHC_CD_N: J2.10(~{INSERT}) R66.1 U1.L5(SDHC_CD_B) U93.4 U93.5
SDHC_CLK: J2.5(CLK/SCLK) R61.2 R68.1 U94.1 U94.8
SDHC_CMD: J2.2(CMD/DIN) R67.1 U1.K3(SDHC_CMD) U93.3 U93.6
SDHC_DAT0: J2.7(D0/DOUT) R60.1 U1.L2(SDHC_DAT0) U94.2 U94.7
SDHC_DAT1: J2.8(D1/RSV) R62.1 U1.K4(SDHC_DAT1) U94.3 U94.6
SDHC_DAT2: J2.9(D2/RSV) R63.1 U1.L3(SDHC_DAT2) U93.1 U93.8
SDHC_DAT3: J2.1(D3/~{CS}) R64.1 U1.L1(SDHC_DAT3) U93.2 U93.7
SDHC_VS: R72.1 U1.D1(IRQ03) ; also on sheet 26
SDHC_WP: J2.11(~{PROTECT}) R65.1 U1.M5(SDHC_WP) U94.4 U94.5
SGMII_RX_N: U25.16(B1-) U27.15(C0+) ; also on sheet 17
SGMII_RX_P: U25.17(B1+) U27.14(C0-) ; also on sheet 17
SGMII_TX_N: U25.18(B0-) U27.13(C1+) ; also on sheet 17
SGMII_TX_P: U25.19(B0+) U27.12(C1-) ; also on sheet 17
SPI_CLK: R865.1 U12.10(B3) ; also on sheet 10 23 24
SPI_CS3_N: U18.12(B1) ; also on sheet 10
SPI_MISO: R54.1 R58.1 U12.12(B1) ; also on sheet 10 23 24
SPI_MOSI: R866.1 U12.11(B2) ; also on sheet 10 23 24
SYS_REFCLK: U1.G15(SYSCLK) ; also on sheet 27
SYS_REFCLK_N: U1.F14(DIFF_SYSCLK_B) ; also on sheet 27
SYS_REFCLK_P: U1.G14(DIFF_SYSCLK) ; also on sheet 27
T2081_EN: R141.2 U25.2(PD) U27.9(SEL) ; also on sheet 26 31
TEMP_DIODE_N: U1.G21(TD1_CATHODE) ; also on sheet 14
TEMP_DIODE_P: U1.E21(TD1_ANODE) ; also on sheet 14
TEST_SEL_N: R83.1 U1.G8(TEST_SEL_B) ; also on sheet 26
VTT: C15.1 C16.1 C17.1 J1.48(VTT/NC) J1.49(VTT/NC) J1.120(VTT) J1.240(VTT) ; also on sheet 31
XFI_RX_N: C60.1 ; also on sheet 21
XFI_RX_P: C59.1 ; also on sheet 21
XFI_TX_N: U1.AE10(SD1_TX0_N) ; also on sheet 21
XFI_TX_P: U1.AD10(SD1_TX0_P) ; also on sheet 21
XVDD: R140.1 ; also on sheet 12
N16747459: R1.2 U1.U28(D1_MDIC1)
N16747463: R3.2 U1.P28(D1_MDIC0)
N16800565: R42.1 U4.53(~{BYTE})
N16800570: R41.1 U4.16(~{WP}/ACC)
N16800621: R44.1 U4.17(RDY/~{BUSY})
N16807910: R51.1 U6.34(DNU34/VCCQ) U6.39(DNU39/VCCQ)
N16808071: R52.1 U6.25(DNU25/VSSQ) U6.48(DNU48/VSSQ)
N16809639: R46.1 U6.10(~{CE2})
N16810401: R45.1 U6.9(~{CE1}) U7.11(B2)
N16811518: U6.17(ALE) U7.9(B4)
N16821274: R12.1 U1.A17(IFC_CLK0)
N16821816: R5.1 U1.E14(IFC_PERR_B)
N16864329: R58.2 U13.8(SO) U15.2(SO)
N16864338: R55.1 R866.2 U13.15(SI) U15.5(SI)
N16864354: R865.2 U13.16(SCK) U15.6(SCK)
N16864366: R56.1 U12.9(B4) U13.7(~{CS}) U15.1(~{CS})
N16864378: R57.1 U13.1(~{HOLD}) U13.9(~{WP}) U15.3(~{WP}) U15.7(~{HOLD})
N17040696: R59.1 U1.N1(SPI_CLK)
N17040868: R61.1 U1.K1(SDHC_CLK)
N17059126: R117.1 U1.AE7(EC2_TXD0)
N17059132: R118.1 U1.AF7(EC2_TXD1)
N17059135: R120.1 U1.AF6(EC2_TXD2)
N17059138: R122.1 U1.AG5(EC2_TXD3)
N17059149: R124.1 R126.1 U1.AF8(EC2_TX_CTL)
N17059152: C56.1 R128.1 U1.AE8(EC2_GTX_CLK)
N17059643: R130.1 U1.L6(EMI2_MDC)
N17059732: R121.2 U1.AC3(EC1_TXD3)
N17059733: R116.2 U1.AE4(EC1_TXD1)
N17059734: R119.2 U1.AD3(EC1_TXD2)
N17059735: R115.2 U1.AE3(EC1_TXD0)
N17059985: R123.2 R125.2 U1.AF4(EC1_TX_CTL)
N17060054: C55.2 R127.2 U1.AF3(EC1_GTX_CLK)
N17060498: R129.2 U1.AH3(EMI1_MDC)
N17072443: R106.2 TP2.1(TP) U1.B17(RTC)
N17081807: C59.2 U1.AH10(SD1_RX0_P)
N17081810: C60.2 U1.AG10(SD1_RX0_N)
N17081955: C63.2 U1.AH11(SD1_RX1_P)
N17081957: C64.2 U1.AG11(SD1_RX1_N)
N17082045: C61.2 U1.AG13(SD1_RX2_N)
N17082047: C65.2 U1.AH13(SD1_RX2_P)
N17082121: C62.2 U1.AH14(SD1_RX3_P)
N17082123: C66.2 U1.AG14(SD1_RX3_N)
N17082319: R140.2 U1.Y20(SD1_IMP_CAL_TX)
N17082346: R139.2 U1.AA12(SD1_IMP_CAL_RX)
N17093364: R137.2 TP9.1(TP) U1.AE5(TSEC_1588_TRIG_IN2)
N17093369: R136.2 TP7.1(TP) U1.AB6(TSEC_1588_TRIG_IN1)
N17093378: R135.2 TP6.1(TP) U1.AC8(TSEC_1588_CLK_IN)
N17109189: R92.1 U1.V2(IIC3_SCL)
N17109201: R93.1 U1.W3(IIC3_SDA)
N17109221: R95.1 U1.AA3(IIC4_SCL)
N17109223: R97.1 U1.AB3(IIC4_SDA)
N17109289: Q1.2(S) R89.1 U1.W1(IIC1_SCL)
N17109292: Q2.2(S) R88.1 U1.V1(IIC1_SDA)
N17109295: R87.1 U1.V3(IIC2_SCL) U19.14(SCL)
N17109336: R86.1 U1.Y3(IIC2_SDA) U19.15(SDA)
N17112712: R99.2 U19.3(~{RESET})
N17112758: R104.2 U1.C20(FA_ANALOG_G_V)
N17112821: R105.2 U1.B20(FA_ANALOG_PIN)
N17112937: R84.1 U1.F9(SCAN_MODE_B)
N17233442: R71.1 U1.E9(IRQ02)
N17233455: R73.1 U1.D4(IRQ04)
N17270978: R74.1 U1.D5(IRQ05)
N17271002: R77.1 U1.AB1(IRQ08)
N17271631: R82.1 U1.F19(TMP_DETECT_B)
N17321001: R103.1 U21.4(O)
N17321019: D1.2 R103.2
N17423481: J3.5 R112.2
N17423546: J3.6 R108.1
N17481068: R100.2 U1.R5(DMA1_DDONE0_B)
N17694594: U6.16(CLE) U7.10(B3)
N17694666: U6.8(~{RE}) U7.12(B1)
N17694695: U6.18(~{WE}) U11.12(B1)
N17694723: U6.19(~{WP}) U11.11(B2)
N17736577: R17.1 SW1.16
N17736598: R19.1 SW1.15
N17736619: R21.1 SW1.14
N17736629: R23.1 SW1.13
N17736659: R25.1 SW1.12
N17736669: R27.1 SW1.11
N17736681: R29.1 SW1.10
N17736695: R31.1 SW1.9
N17736739: R33.1 SW2.16
N17736751: R34.1 SW2.15
N17736763: R35.1 SW2.14
N17736781: R36.1 SW2.13
N17736801: R39.1 SW2.11
N17736803: R37.1 SW2.12
N17736817: R38.1 SW2.10
N17736835: R40.1 SW2.9
N18287015: R138.1 U23.4(C) U24.4(C)
N19620774: C68.2 U1.AA14(SD1_REF_CLK1_N)
N19620777: C67.2 U1.AB14(SD1_REF_CLK1_P)
N20473911: R811.1 U1.C15(IFC_PAR0)
N20516568: TP1.1(TP) U1.E6(CLK_OUT)
N20517420: TP3.1(TP) U1.AD7(TSEC_1588_CLK_OUT)
N20517422: TP4.1(TP) U1.AF5(TSEC_1588_ALARM_OUT1)
N20517434: TP5.1(TP) U1.AC7(TSEC_1588_ALARM_OUT2)
N20517436: TP8.1(TP) U1.AE6(TSEC_1588_PULSE_OUT1)
N20517448: TP10.1(TP) U1.AD8(TSEC_1588_PULSE_OUT2)
N20562248: TP11.1(TP) U1.Y15(SD1_PLL1_TPA)
N20562257: TP12.1(TP) U1.AB15(SD1_PLL1_TPD)
N20562271: TP13.1(TP) U1.Y19(SD1_PLL2_TPA)
N20562273: TP14.1(TP) U1.AB19(SD1_PLL2_TPD)
N22257590: R14.1 U2.2(1Q1)
N22257592: R15.1 U2.3(1Q2)
N22257594: R16.1 U2.5(1Q3)
N22258098: R20.1 U2.8(1Q5)
N22258100: R22.1 U2.9(1Q6)
N22258102: R24.1 U2.11(1Q7)
N22258104: R26.1 U2.12(1Q8)
N22258216: R18.1 U2.6(1Q4)
N22258634: R28.1 U2.13(2Q1)
N22258636: R30.1 U2.14(2Q2)
N22258638: R32.1 U2.16(2Q3)
N22476599: R49.2 R50.2 U7.4(A4)

Not connected (* = marked no-connect by the designer): J1 126(NC/~{DQS9})* 135(NC/~{DQS10})* 144(NC/~{DQS11})* 153(NC/~{DQS12})* 162(NC/~{DQS17})* 167(TEST/NC)* 187(~{EVENT}/NC)* 204(NC/~{DQS13})* 213(NC/~{DQS14})* 222(NC/~{DQS15})* 231(NC/~{DQS16})*; J3 2* 8* 10* 14*; U1 A14(IFC_BCTL)* A16(IFC_NDDQS)* A19(IFC_CLK1)* AA5(DMA2_DACK0_B)* AC4(EC1_TX_ER)* C3(EVT4_B)* C4(EVT1_B)* C16(IFC_CS3_B)* C17(IFC_CS5_B)* C19(IFC_CS7_B)* D6(EVT0_B)* D18(IFC_CS6_B)* E17(IFC_CS4_B)* F21(TEST_OUT1)* H21(TEST_OUT0)* J20(D1_TPA)* K22(TEST_OUT4)* M22(TEST_OUT5)* P22(TEST_OUT7)* U22(TEST_OUT6)* V21(TEST_OUT3)* W21(TEST_OUT2)* Y5(DMA2_DDONE0_B)* Y21(TEST_OUT8)*; U2 17(2Q4)* 19(2Q5)* 20(2Q6)* 22(2Q7)* 23(2Q8)*; U4 27(NC1)* 28(NC2)* 30(NC3)*; U6 1(NC1)* 2(NC2)* 3(NC3)* 4(NC4)* 5(NC5)* 6(R/~{B2})* 11(NC11)* 14(NC14)* 15(NC15)* 20(NC20)* 21(NC21)* 22(NC22)* 23(NC23)* 24(NC24)* 26(DNU26)* 27(NC27)* 28(NC28)* 33(NC33)* 35(DNU35)* 38(DNU38)* 40(NC40)* 45(NC45)* 46(NC46)* 47(NC47)*; U7 5(NC1)* 14(NC2)* 15(NC3)*; U11 3(A3)* 4(A4)* 5(NC1)* 9(B4)* 10(B3)* 14(NC2)* 15(NC3)*; U12 5(NC1)* 14(NC2)* 15(NC3)*; U13 3(NC1)* 4(NC2)* 5(NC3)* 6(NC4)* 11(NC5)* 12(NC6)* 13(NC7)* 14(NC8)*; U18 4(A4)* 5(NC1)* 9(B4)* 14(NC2)* 15(NC3)*; U20 5(NC1)* 14(NC2)* 15(NC3)*; U25 12(C1-)* 13(C1+)* 14(C0-)* 15(C0+)*; U98 5(NC1)* 14(NC2)* 15(NC3)*; U99 5(NC1)* 14(NC2)* 15(NC3)*

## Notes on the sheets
sheet 1
- T1040RDB
- Page  Description
- Version Control
- 1
- SCHEMATIC PAGE LISTING
- Version
- Date
- Modifications
- 2
- SYSTEM BLOCK DIAGRAM
- 3
- T1040 DDR3L MEMORY INTERFACE
- V0.1
- 2013/06
- First release of Schematics
- 4
- T1040 IFC INTERFACE
- 5
- T1040 NOR and NAND FLASH INTERFACE
- V1.0
- 2013/10
- Released to Manufacturing
- 6
- T1040 SPI FLASH and SDHC INTERFACE
- 7
- T1040 SYSTEM LOGIC INTERFACE
- V2.0
- 2014/01
- Add SD_REFCLK1_SEL to select SerDes PLL1 input clock frequency
- Change the direction of the battery holder
- 8
- T1040 ETHERNET and SERDES INTERFACE
- 9
- SERDES MUX/DEMUX SWITCHs
- 10
- T1040 QE INTERFACE
- 11
- T1040 USB INTERFACE
- 12
- T1040 POWER SUPPLY
- 13
- T1040 PLL FILTERs and GROUND
- 14
- T1040 DUART INTERFACE
- 15
- RGMII ETHERNET PORT 1
- 16
- RGMII ETHERNET PORT 2
- Variants  Description
- 17
- SGMII ETHERNET PORT
- INTERPOSER
- INTERPOSER version (normal + VIT)
- 18
- QSGMII PHY 1
- T1040/T2081 RDB
- T1040RDB version (normal + VNIT)
- 19
- QSGMII PHY 2
- 20
- QSGMII ETHERNET PORTs
- 21
- 10G EDC PHY and SFP+ CONNECTOR
- 22
- PCIe X1/X4 SLOT, MINI PCIe and SATA CONNECTORs
- 23
- POTS 1&2 INTERFACE
- 24
- POTS 3&4 INTERFACE
- 25
- POTS VBAT POWER SUPPLY
- 26
- CPLD
- 27
- SYSTEM CLOCK GENERATORs
- 28
- SYSTEM CLOCK GENERATORs (cont.)
- 29
- T1040 CORE POWER CONVERTOR
- 30
- SYSTEM POWER CONVERTORs
- 31
- SYSTEM POWER SWITCHs
- All information is subject to change without notice.
  No warranty, expressed or applied, is made as to the
  accuracy of the information contained herein. This
  schematic is provided for reference purposes only.
  Contact your Freescale representative to obtain the
  latest information on this product.
- 32
- SYSTEM POWER INPUT
- 33
- MECHANICALs
- 34
- CHANGE LIST
sheet 2
- SYSTEM BLOCK DIAGRAM
- RJ45 2x1
- RJ45
- RS232
- RS232 XCVR
- UART1
- DDR3L
- DDR3L UDIMM
- ATX Power
- I2C1
- 72bit, 4GB
- 12V
- RS232
- UART2
- 5V
- RJ45
- RS232 XCVR
- IFC
- NOR FLASH
- 16bit, 128MB
- 1.0V
- VCORE
- USB1
- I2C EEPROM
- 1.35V
- USB Conn.
- USB1
- USB Protect &
  Power Switch
- USB2
- AT24C256
- 1.5V
- Power
  Regulators
- TypeA x2
- USB2
- USB CTL
- NAND FLASH
- 1.8V
- 8bit, 1GB
- 2.5V
- SGMII
- Thermal Monitor
- ADT7461
- 3.3V
- MDI
- MDI
- SGMII PHY
- 5V
- RJ45
- Magnetics
- RTL8211DN
- EMI1
- ALTERA CPLD
- 12V
- EPM570G
- SPI
- SPI FLASH
- RGMII
- 64MB
- RJ45 2x1
- RJ45
- MDI
- Magnetics
- MDI
- RGMII PHY
- RTL8211E-VB
- SDHC
- SDHC
- SD Card
- RGMII
- Protect
- SDHC/SDXC
- T1040 ONLY!
- RJ45
- MDI
- Magnetics
- MDI
- RGMII PHY
- T1040
- RTL8211E-VB
- JTAG
- JTAG
- /T2081
- OVDD<->3.3V
- COP Conn.
- TIP/RING
- Tip/Ring
- TDM
- FXS
- Protect
- Dual SLAC&SLIC
- PCIe
- T1040 ONLY!
- FXS
- TIP/RING
- Protect
- Tip/Ring
- Le88266
- SPI
- I2C2CH4
- PEX x1/4 SLOT
- x1 For T1040; x4 For T2081
- RJ11 x4
- TIP/RING
- Tip/Ring
- FXS
- Protect
- Dual SLAC&SLIC
- PCIe
- TIP/RING
- Tip/Ring
- Le88266
- I2C2CH1
- Mini PCIe Conn.
- T1040 ONLY!
- FXS
- Protect
- PCIe
- FXO
- Conn.
- Relay
- VBAT
- I2C2CH2
- Mini PCIe Conn.
- T1040 ONLY!
- MDI
- MDI
- SATA
- SATA Conn.
- T1040 ONLY!
- MDI
- MDI
- QSGMII
- QSGMII
- T1040 ONLY!
- MDI
- MAGNETICS
- MDI
- PHY
- RJ45 x8
- MDI
- MDI
- F104S8A
- EMI1
- MDI
- MDI
- T1040 ONLY!
- MDI
- MDI
- QSGMII
- QSGMII
- QE
- MDI
- MDI
- PHY
- SPI
- TDM Riser Card Conn.
- MDI
- MDI
- F104S8A
- T2081 ONLY!
- XFI
- XFI
- SFP+
- 10G PHY
- CS4315
- EMI2
- I2C2CH3
sheet 3
- T1040 DDR3L MEMORY INTERFACE
- 1.35V DDR3L SDRAM UDIMM
- 4GB (x72, ECC, DR)
- Micron MPN(4GB,1600): MT18KSF51272AZ-1G6
- Micron MPN(2GB,2133): MT9JSF25672AZ-2G1
- T1040 REV 1.0: 162 ohm
- T2081 REV 1.0: 187 ohm
- SPD ADDR = 0x51
sheet 4
- T1040 IFC INTERFACE
- FOR T1040/T2081, OVDD = 1.8V
- FOR INTERPOSER, OVDD = 3.3V
- CS0: NOR or NAND
- CS1: NAND or NOR
- CS2: CPLD
- Interposer por cfg
- cfg_rcw_src0
- cfg_rcw_src2
- cfg_rcw_src3
- cfg_test_port_dis
- cfg_elbc_ecc
- cfg_dram_type
- cfg_xvdd_sel
- 1 for 1.5V
- cfg_rcw_src4
- cfg_rcw_src1
- T1040 RESET CONFIGURATION
- cfg_rcw_src[0:8]
- 0_0010_0111: NOR FLASH BOOT
- 0_0100_0000: SD CARD BOOT
- 0_0100_0101: SPI BOOT
- 1_0001_1001: NAND FLASH BOOT
- cfg_rcw_src0
- cfg_rcw_src1
- cfg_rcw_src2
- cfg_rcw_src3
- cfg_rcw_src4
- cfg_rcw_src5
- cfg_rcw_src6
- cfg_rcw_src7
- cfg_rcw_src8
- cfg_ifc_te
- cfg_pll_config_sel_b
- 1: TE logic 0
- cfg_por_ainit
- cfg_svr0
- cfg_svr1
- cfg_dram_type
- cfg_dram_type
- For T1040: 0: DDR3L
- cfg_rsp_dis
- For T2081 1: DDR3L
sheet 5
- T1040 NOR and NAND FLASH INTERFACE
- FOR T1040/T2081, OVDD = 1.8V
- FOR INTERPOSER, OVDD = 3.3V
- 128MB 16-BIT NOR FLASH
- 1GB 8-BIT NAND FLASH
- On Interposer ONLY, NAND AVD is routed on PAR1
- On Interposer, NAND MPN: K9F5608U0D
sheet 6
- T1040 SPI FLASH and SDHC INTERFACE
- 64MB SERIAL FLASH
- SPI OPERATES AT 1.8V FOR T1040/T2081
- 3.3V FOR INTERPOSER
- EVDD CAN BE 3.3V or 1.8V
- CO-LAYOUT
- SD CARD FOR T1040 ONLY!
sheet 7
- T1040 SYSTEM LOGIC INTERFACE
- TEST_SEL_B
- FOR T1040, PULL-DOWN
- FOR T1020/T2081, PULL-UP
- FOR INTERPOSER/T1040, DVDD = 3.3V
- FOR T2081, DVDD = 2.5V
- FOR T2081, KEEP SLAC RESET
- cfg_test_port_mux_sel
- XVDD use 1.35V
- I2C ADDR = 0x77
- cfg_xvdd_sel
- LABEL = ASLEEP
sheet 8
- T1040 ETHERNET and SERDES INTERFACE
- EC1&EC2 OPERATE AT 2.5V EXCEPT EMI2 OPERATES AT 1.8V
sheet 9
- SERDES MUX/DEMUX SWITCHs
